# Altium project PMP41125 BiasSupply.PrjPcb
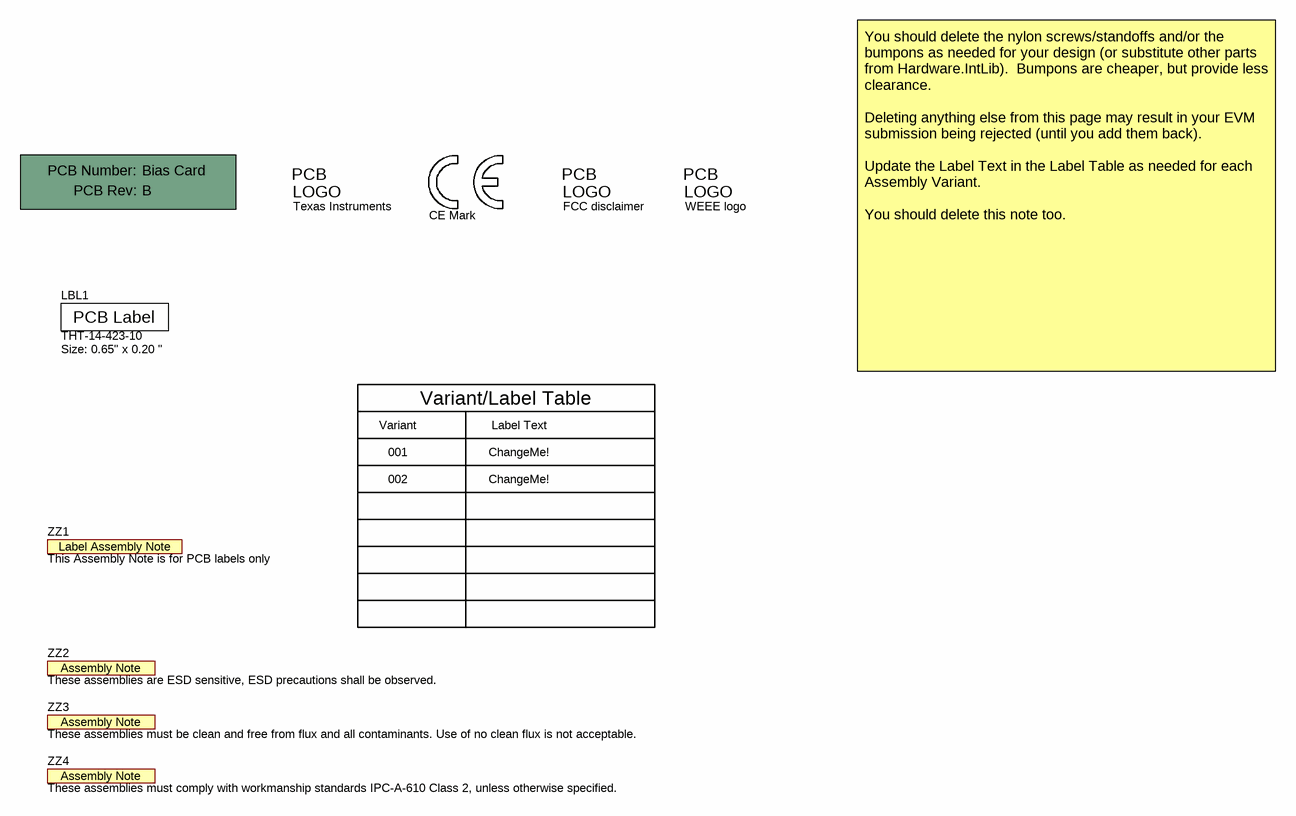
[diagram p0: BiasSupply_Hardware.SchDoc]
CopyrightYear: 2024; PCB_Layout: Daniel Gao; PCB_Rev: B; PRJ_Customer: Public Release; PRJ_Engineer: Forest Fu; PRJ_Number: Bias Card; PRJ_Title: HV-LV DCDC reference design; SCH_Rev: B; TechSupport: http://www.ti.com/support; TID: PMP41125
5 sheets, 169 parts. Net scope: flat (ports and power ports of the same name join across sheets).
Board file: BiasSupply.PcbDoc
Sheets:
  BiasSupply_Hardware.SchDoc
  BiasSupply-TPS552872-Q1.SchDoc
  BiasSupply-LM74202-Q1.SchDoc
  BiasSupply-SN6507-Q1.SchDoc
  BiasSupply-LM61440-Q1.SchDoc

## Sheet BiasSupply_Hardware.SchDoc
size 431 x 279 mm; Date: Not shown in title block; ApprovedBy: Not shown in title block; CheckedBy: Not shown in title block; Author: Not shown in title block; CompanyName: Not shown in title block; Engineer: Not shown in title block; Organization: Not shown in title block; Address1: Not shown in title block; Address2: Not shown in title block; Address3: Not shown in title block; Address4: Not shown in title block; DocumentNumber: 3; Revision: Use project parameter SCH_Rev; SheetNumber: 3; SheetTotal: 3; PageSetup: Record=PageOptions¦CenterHorizontal=True¦CenterVertical=True¦PrintScale=1.00¦XCorrection=1.00¦YCorrection=1.00¦PrintKind=0¦BorderSize=5000000¦LeftOffset=0¦BottomOffset=0¦Orientation=2¦PaperLength=1000¦PaperWidth=1000¦Scale=100¦PaperSource=15¦PrintQuality=600¦MediaType=1¦DitherType=10¦PaperKind=Letter¦PrintScaleMode=1

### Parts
!PCB  Printed Circuit Board  (value not drawn)  (mechanical)
LBL1  THT-14-423-10  Note: Size: 0.65" x 0.20 "  [Label_650x200]
Logo1  Texas Instruments  [TI_Stacked_Overlay_Small]  (no BOM)
Logo2  CE Mark  [CE_Mark_5mm]  (no BOM)
Logo3  FCC disclaimer  [FCC_disclaimer]  (no BOM)
Logo4  WEEE logo  [WEEE_Minimum]  (no BOM)
ZZ1  This Assembly Note is for PCB labels only  [AssemblyNoteLabel]  (no BOM)
ZZ2  These assemblies are ESD sensitive, ESD precautions shall be observed.  [AssemblyNote]  (no BOM)
ZZ3  These assemblies must be clean and free from flux and all contaminants. Use of no clean flux is not acceptable.  [AssemblyNote]  (no BOM)
ZZ4  These assemblies must comply with workmanship standards IPC-A-610 Class 2, unless otherwise specified.  [AssemblyNote]  (no BOM)

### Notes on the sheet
- Variant
- Variant/Label Table
- Label Text
- You should delete the nylon screws/standoffs and/or the bumpons as needed for your design (or substitute other parts from Hardware.IntLib).  Bumpons are cheaper, but provide less clearance.
  Deleting anything else from this page may result in your EVM submission being rejected (until you add them back).
  Update the Label Text in the Label Table as needed for each Assembly Variant.
  You should delete this note too.
- 001
- 002
- ChangeMe!

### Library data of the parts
!PCB = CMP-0003618-2: Manufacturer: Any; PartNumber: Bias Card
LBL1 = CMP-0003625-1: Thermal Transfer Printable Labels, 0.650" W x 0.200" H - 10,000 per roll; Manufacturer: Brady; CompType: Label
Logo1 = CMP-0074838-1: Texas Instrument Corporate Signature; SymbolCreator: a0412235; Lib Reference: TI_Logo; Library Reference: Logo
Logo2 = CMP-0074844-1: SymbolCreator: a0412235
Logo3 = CMP-0074847-1: FCC_disclaimer; Library Reference: Logo
Logo4 = CMP-0074769-1
ZZ1 = CMP-0003616-3
ZZ2 = CMP-0077236-1
ZZ3 = CMP-0077237-1
ZZ4 = CMP-0077238-1

## Sheet BiasSupply-TPS552872-Q1.SchDoc
size 431 x 279 mm; Date: Not shown in title block; ApprovedBy: Not shown in title block; CheckedBy: Not shown in title block; Author: Not shown in title block; CompanyName: Not shown in title block; DrawnBy: Daniel Gao; Engineer: Not shown in title block; Organization: Not shown in title block; Address1: Not shown in title block; Address2: Not shown in title block; Address3: Not shown in title block; Address4: Not shown in title block; DocumentNumber: 2; Revision: Use project parameter SCH_Rev; SheetNumber: 2; SheetTotal: 3; PageSetup: Record=PageOptions¦CenterHorizontal=True¦CenterVertical=True¦PrintScale=1.00¦XCorrection=1.00¦YCorrection=1.00¦PrintKind=0¦BorderSize=5000000¦LeftOffset=0¦BottomOffset=0¦Orientation=2¦PaperLength=1000¦PaperWidth=1000¦Scale=100¦PaperSource=15¦PrintQuality=600¦MediaType=1¦DitherType=10¦PaperKind=Letter¦PrintScaleMode=1
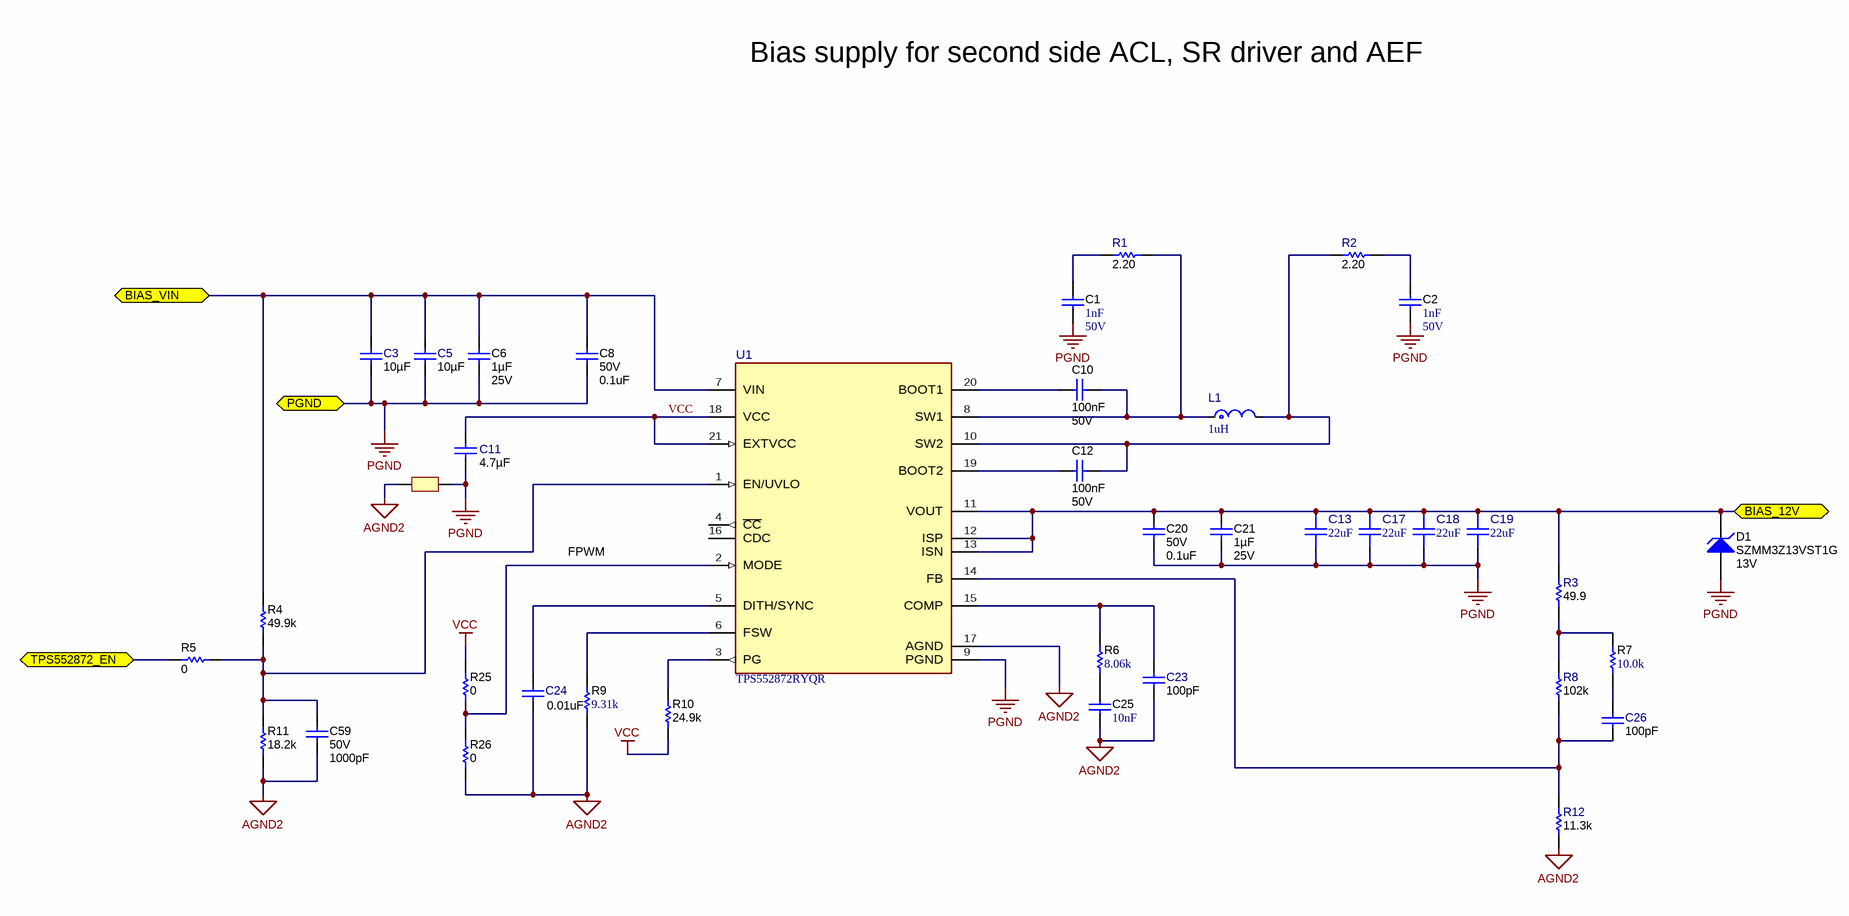
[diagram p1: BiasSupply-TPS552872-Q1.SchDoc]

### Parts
C1  Cap_F: 1nF  VDC_V: 50V  [0603]  (hidden comment: C0603C102J5RACAUTO)
C2  Cap_F: 1nF  VDC_V: 50V  [0603]  (hidden comment: C0603C102J5RACAUTO)
C3  ValueDisplayed: 10µF  [1206_190]  (hidden comment: CGA5L1X7R1H106K160AC)
C5  ValueDisplayed: 10µF  [1206_190]  (hidden comment: CGA5L1X7R1H106K160AC)
C6  Cap_F: 1µF  VDC_V: 25V  [0603L]  (hidden comment: CGA3E1X7R1E105K080AC)
C8  VDC_V: 50V  ValueDisplayed: 0.1uF  [0402]  (hidden comment: GCM155R71H104KE02D)
C10  Cap_F: 100nF  VDC_V: 50V  [0603L]  (hidden comment: CGA3E2X7R1H104K080AA)
C11  ValueDisplayed: 4.7µF  [0603]  (hidden comment: GRT188R61C475KE13D)
C12  Cap_F: 100nF  VDC_V: 50V  [0603L]  (hidden comment: CGA3E2X7R1H104K080AA)
C13  ValueDisplayed: 22uF  [FP-CGA6P3X7R1E226M250AB_1210-MFG]  (hidden comment: CGA6P3X7R1E226M250AB)
C17  ValueDisplayed: 22uF  [FP-CGA6P3X7R1E226M250AB_1210-MFG]  (hidden comment: CGA6P3X7R1E226M250AB)
C18  ValueDisplayed: 22uF  [FP-CGA6P3X7R1E226M250AB_1210-MFG]  (hidden comment: CGA6P3X7R1E226M250AB)
C19  ValueDisplayed: 22uF  [FP-CGA6P3X7R1E226M250AB_1210-MFG]  (hidden comment: CGA6P3X7R1E226M250AB)
C20  VDC_V: 50V  ValueDisplayed: 0.1uF  [0402]  (hidden comment: GCM155R71H104KE02D)
C21  Cap_F: 1µF  VDC_V: 25V  [0603L]  (hidden comment: CGA3E1X7R1E105K080AC)
C23  ValueDisplayed: 100pF  [0402]  (hidden comment: Capacitor)
C24  ValueDisplayed: 0.01uF  [0402]  (hidden comment: CGA2B3X7R1H103K050BB)
C25  ValueDisplayed: 10nF  [0402]  (hidden comment: CGA2B3X7R1H103K050BB)
C26  ValueDisplayed: 100pF  [0402]  (hidden comment: Capacitor)
C59  VDC_V: 50V  ValueDisplayed: 1000pF  [0402]  (hidden comment: GCM155R71H102KA37D)
D1  SZMM3Z13VST1G  value 13V  [SOD-323]
L1  value 1uH  [FP-XGL5030-102MEC_SMT_IND_5MM28_5MM48-MFG]  (hidden comment: XGL5030-102MEC)
NT1  Net-Tie  [Net-Tie_50milWide_30milLong]  (value not drawn)  (net tie, no BOM)
R1  ValueDisplayed: 2.20  [1206]  (hidden comment: Resistor)
R2  ValueDisplayed: 2.20  [1206]  (hidden comment: Resistor)
R3  ValueDisplayed: 49.9  [0402]  (hidden comment: Resistor)
R4  ValueDisplayed: 49.9k  [0402]  (hidden comment: CRCW040249K9FKED)
R5  ValueDisplayed: 0  [0402]  (hidden comment: CRCW04020000Z0ED)
R6  ValueDisplayed: 8.06k  [0402]  (hidden comment: CRCW04028K06FKED)
R7  ValueDisplayed: 10.0k  [0402]  (hidden comment: CRCW040210K0FKED)
R8  ValueDisplayed: 102k  [0402]  (hidden comment: Resistor)
R9  ValueDisplayed: 9.31k  [0402]  (hidden comment: CRCW04029K31FKED)
R10  ValueDisplayed: 24.9k  [0402]  (hidden comment: CRCW040224K9FKED)
R11  ValueDisplayed: 18.2k  [0402]  (hidden comment: CRCW040218K2FKED)
R12  ValueDisplayed: 11.3k  [0402]  (hidden comment: Resistor)
R25  ValueDisplayed: 0  [0402]  (hidden comment: CRCW04020000Z0ED)
R26  ValueDisplayed: 0  [0402]  (hidden comment: CRCW04020000Z0ED)
U1  TPS552872RYQR  [RYQ0021A-MFG]

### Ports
BIAS_12V (bidir), BIAS_VIN (bidir), PGND (bidir), TPS552872_EN (bidir)

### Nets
AGND2: C23.2 C24.2 C25.2 C59.2 NT1.1 R9.1 R11.1 R12.1 R26.1 U1.17(AGND)
PGND: C1.2 C2.2 C3.2 C5.2 C6.1 C8.2 C11.2 C13.2 C17.2 C18.2 C19.2 C20.2 C21.1 D1.2(A) NT1.2 U1.9(PGND) ; port PGND
VCC: C11.1 R10.1 R25.2 U1.18(VCC) U1.21(EXTVCC)
BIAS_12V: C13.1 C17.1 C18.1 C19.1 C20.1 C21.2 D1.1(K) R3.2 U1.11(VOUT) U1.12(ISP) U1.13(ISN) ; port BIAS_12V
BIAS_VIN: C3.1 C5.1 C6.2 C8.1 R4.2 U1.7(VIN) ; port BIAS_VIN
TPS552872_EN: R5.1 ; port TPS552872_EN
NetC1_1: C1.1 R1.2
NetC2_1: C2.1 R2.1
NetC10_1: C10.1 L1.1 R1.1 U1.8(SW1)
NetC10_2: C10.2 U1.20(BOOT1)
NetC12_1: C12.1 L1.2 R2.2 U1.10(SW2)
NetC12_2: C12.2 U1.19(BOOT2)
NetC23_1: C23.1 R6.2 U1.15(COMP)
NetC24_1: C24.1 U1.5(DITH/SYNC)
NetC25_1: C25.1 R6.1
NetC26_1: C26.1 R7.1
NetC26_2: C26.2 R8.1 R12.2 U1.14(FB)
NetC59_1: C59.1 R4.1 R5.2 R11.2 U1.1(EN/UVLO)
NetR3_1: R3.1 R7.2 R8.2
NetR9_2: R9.2 U1.6(FSW)
NetR10_2: R10.2 U1.3(PG)
NetR25_1: R25.1 R26.2 U1.2(MODE)

Not connected (* = marked no-connect by the designer): U1 4(~{CC}) 16(CDC)

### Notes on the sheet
- Bias supply for second side ACL, SR driver and AEF
- FPWM

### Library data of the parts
C1 C2 = CMP-0006844-4: CAP, CERM, 1000 pF, 50 V, +/- 5%, X7R, AEC-Q200 Grade 1, 0603; Manufacturer: Kemet; TaMin_C: -55°C; Polarized: N; SizeAreaWB_mm2: 4.68; Value1: Unknown; U/M: EA; Value: 1000pF; TaMax_C: 125°C; SizeZ_mm: 1; SizeX_mm: 1.6; SizeY_mm: 0.8; SizeArea_mm2: 1.28; AEC Qualified: Y; AEC Category: Q200
C3 C5 = CMP-0085950-1: CAP, CERM, 10 µF, 50 V,+/- 10%, X7R, AEC-Q200 Grade 1, 1206; Manufacturer: TDK; SizeZ_mm: 1.9; Value: 10uF; Value2: 50V; Cap_Case: 1206; AEC Grade: 1; TaMin_C: -55°C; U/M: EA; CompType: Capacitor; SizeArea_mm2: 5.12; TaMax_C: 125°C; AEC Qualified: Y; AEC Category: Q200; SizeX_mm: 3.2; SizeY_mm: 1.6; Polarized: N; SizeAreaWB_mm2: 10.92
C6 C21 = CMP-0076705-2: CAP, CERM, 1 µF, 25 V,+/- 10%, X7R, AEC-Q200 Grade 1, 0603; Manufacturer: TDK; SizeAreaWB_mm2: 4.68; SizeArea_mm2: 1.28; AEC Qualified: Y; AEC Category: Q200; Value: 1uF; TaMax_C: 125°C; SizeZ_mm: 1.0; AEC Grade: 1; Polarized: N; TaMin_C: -55°C; SizeY_mm: 0.8; U/M: EA; SizeX_mm: 1.6; Cap_Case: 1.6x0.8x0.8mm
C8 C20 = CMP-0006356-2: CAP, CERM, 0.1 uF, 50 V, +/- 10%, X7R, AEC-Q200 Grade 1, 0402; Manufacturer: MuRata; TaMin_C: -55°C; Polarized: N; SizeAreaWB_mm2: 3; Value1: Unknown; U/M: EA; Value: 0.1uF; TaMax_C: 125°C; SizeZ_mm: 0.6; SizeX_mm: 1; SizeY_mm: 0.5; AEC Qualified: Y; Cap_F: 100nF; AEC Category: Q200
C10 C12 = CMP-0007078-1: CAP, CERM, 0.1 uF, 50 V, +/- 10%, X7R, AEC-Q200 Grade 1, 0603; Manufacturer: TDK; TaMin_C: -55°C; ESR_ohm: 29.6m; Polarized: N; SizeAreaWB_mm2: 4.68; Value1: 0.0296 ohm; U/M: EA; Value: 0.1uF; TaMax_C: 125°C; SizeZ_mm: 1; SizeX_mm: 1.6; SizeY_mm: 0.8; Cap_Case: 0603; SizeArea_mm2: 1.28; AEC Qualified: Y; IRMS_A: 971.99mA; AEC Category: Q200
C11 = CMP-0081052-1: CAP, CERM, 4.7 µF, 16 V,+/- 10%, X5R, AEC-Q200 Grade 3, 0603; Manufacturer: MuRata; SizeAreaWB_mm2: 4.68; SizeArea_mm2: 1.28; AEC Qualified: Y; AEC Category: Q200; Value: 4.7uF; TaMax_C: 85°C; SizeZ_mm: 1; AEC Grade: 3; Polarized: N; TaMin_C: -55°C; VDC_V: 16V; SizeY_mm: 0.8; U/M: EA; CompType: Capacitor; SizeX_mm: 1.6
C13 C17-C19 = CMP-0036912-1: Cap Ceramic 22uF 25V X7R 20% Pad SMD 1210 +125°C Automotive T/R; Manufacturer: TDK; AEC Grade: Grade 1; AEC Qualified: Yes; Cap_F: 22µF; SizeZ_mm: 2.8mm; TempCo: 15%; Tolerance_%: 0.2%; Value: 22µF
C23 C26 = CMP-0006308-2: CAP, CERM, 100 pF, 50 V, +/- 5%, C0G/NP0, AEC-Q200 Grade 1, 0402; PartNumber: CGA2B2C0G1H101J050BA; Manufacturer: TDK; Polarized: N; Value: 100pF; U/M: EA; Value1: Unknown; VDC_V: 50V; TaMin_C: -55°C; TaMax_C: 125°C; SizeArea_mm2: 0.5; SizeAreaWB_mm2: 3; SizeX_mm: 1; SizeZ_mm: 0.6; AEC Category: Q200; AEC Qualified: Y
C24 = CMP-0006324-2: CAP, CERM, 0.01 uF, 50 V, +/- 10%, X7R, AEC-Q200 Grade 1, 0402; Manufacturer: TDK; TaMin_C: -55°C; ESR_ohm: 3.33065d; Polarized: N; SizeAreaWB_mm2: 3; Value1: 0.333065 ohm; U/M: EA; Value: 0.01uF; TaMax_C: 125°C; SizeZ_mm: 0.6; SizeX_mm: 1; SizeY_mm: 0.5; Value2: 50V; CompType: Capacitor; AEC Qualified: Y; Cap_F: 10nF; IRMS_A: 3.23373dA; AEC Category: Q200
C25 = CMP-0006324-2: CAP, CERM, 0.01 uF, 50 V, +/- 10%, X7R, AEC-Q200 Grade 1, 0402; Manufacturer: TDK; TaMin_C: -55°C; ESR_ohm: 0.3331; Polarized: N; SizeAreaWB_mm2: 3; Value1: 0.333065 ohm; U/M: EA; Value: 0.01uF; TaMax_C: 125°C; SizeZ_mm: 0.6; SizeX_mm: 1; SizeY_mm: 0.5; Value2: 50V; AEC Qualified: Y; IRMS_A: 323.373mA; AEC Category: Q200
C59 = CMP-0006354-2: CAP, CERM, 1000 pF, 50 V, +/- 10%, X7R, AEC-Q200 Grade 1, 0402; Manufacturer: MuRata; TaMin_C: -55°C; Polarized: N; SizeAreaWB_mm2: 3; Value1: Unknown; U/M: EA; Value: 1000pF; TaMax_C: 125°C; SizeZ_mm: 0.6; SizeX_mm: 1; SizeY_mm: 0.5; AEC Qualified: Y; Cap_F: 1nF; AEC Category: Q200
D1 = CMP-0085759-1: Diode, Zener, 13 V, 300 mW, AEC-Q101, SOD-323; Manufacturer: ON Semiconductor; AEC Category: Q101; RJA_CperW: 416; SizeX_mm: 2.7; SizeAreaWB_mm2: 8.695; SizeZ_mm: 1; SizeArea_mm2: 3.645; AEC Qualified: Y; SizeY_mm: 1.35; Value1: 0.3W; Power_W: 300mW
L1 = CMP-0091978-1: Shielded Power Inductor, 1uH, 20%, 17.8A IRMS, 5.8mOhm DCR max, AECQ200 Grade1, 5.28x5.48x3.1mm; Manufacturer: Coilcraft; Test Frequency: 1MHz; Shrouded: true; DCR_ohm: 5.8m; Ind_H: 1µH; Material: Composite; TaMin_C: -40°C; TaMax_C: +125°C; Self Resonant Frequency: 52MHz; AEC Qualified: Yes; Isat: 5.9A; SizeZ_mm: 3.1mm
NT1 = CMP-0078142-6: Single point connection between nets.
R1 R2 = CMP-0017777-3: RES, 2.20, 1%, 0.25 W, AEC-Q200 Grade 0, 1206; PartNumber: ERJ-8RQF2R2V; Manufacturer: Panasonic; Value: 2.20; Res_ohm: 2.2; Value_Code: 2R20; Power_W: 250mW; Value2: 0.25W; TempCo: 200 ppm/C; SizeArea_mm2: 5.12; SizeX_mm: 3.2; SizeY_mm: 1.6; SizeZ_mm: 1.35; AEC Category: Q200; AEC Qualified: Y; AEC Grade: 0; SizeAreaWB_mm2: 10.92
R3 = CMP-0026404-2: RES, 49.9, 1%, 0.063 W, AEC-Q200 Grade 0, 0402; PartNumber: CRCW040249R9FKED; Manufacturer: Vishay-Dale; Value: 49.9; Value_Code: 49R9; Power_W: 63mW; Value2: 0.063W; VDC_V: 50V; TempCo: 100 ppm/C; EIA_Code: E96; AEC Category: Q200; AEC Grade: 0; AEC Qualified: Y; SizeArea_mm2: 0.5; SizeX_mm: 1; SizeZ_mm: 0.6
R4 = CMP-0026403-2: RES, 49.9 k, 1%, 0.063 W, AEC-Q200 Grade 0, 0402; Manufacturer: Vishay-Dale; Power_W: 63mW; TempCo: 100 ppm/C; Value_Code: 49k9; Value: 49.9k; EIA_Code: E96; SizeX_mm: 1; SizeY_mm: 0.5; SizeZ_mm: 0.6; Value2: 0.063W; AEC Qualified: Y; VDC_V: 50V; AEC Category: Q200; AEC Grade: 0
R5 R25 R26 = CMP-0026822-3: RES, 0, 5%, 0.063 W, AEC-Q200 Grade 0, 0402; Manufacturer: Vishay-Dale; Power_W: 63mW; TempCo: 200 ppm/C; Value_Code: 0000; Value: 0; EIA_Code: E24; SizeX_mm: 1; SizeY_mm: 0.5; SizeZ_mm: 0.6; Value2: 0.063W; AEC Qualified: Y; VDC_V: 50V; AEC Category: Q200
R6 = CMP-0026588-2: RES, 8.06 k, 1%, 0.063 W, AEC-Q200 Grade 0, 0402; Manufacturer: Vishay-Dale; Power_W: 63mW; TempCo: 100 ppm/C; Value_Code: 8k06; Value: 8.06k; EIA_Code: E96; SizeX_mm: 1; SizeY_mm: 0.5; SizeZ_mm: 0.6; Value2: 0.063W; AEC Qualified: Y; VDC_V: 50V; AEC Category: Q200; AEC Grade: 0
R7 = CMP-0025958-3: RES, 10.0 k, 1%, 0.063 W, AEC-Q200 Grade 0, 0402; Manufacturer: Vishay-Dale; Power_W: 63mW; TempCo: 100 ppm/C; Value_Code: 10k0; Value: 10.0k; EIA_Code: E96; Res_ohm: 10k; SizeX_mm: 1; SizeY_mm: 0.5; SizeZ_mm: 0.6; Value2: 0.063W; AEC Qualified: Y; VDC_V: 50V; AEC Category: Q200; AEC Grade: 0
R8 = CMP-0025952-3: RES, 102 k, 1%, 0.063 W, AEC-Q200 Grade 0, 0402; PartNumber: CRCW0402102KFKED; Manufacturer: Vishay-Dale; Value: 102k; Power_W: 63mW; Value2: 0.063W; VDC_V: 50V; TempCo: 100 ppm/C; SizeArea_mm2: 0.5; SizeX_mm: 1; SizeZ_mm: 0.6; EIA_Code: E96; AEC Category: Q200; AEC Qualified: Y; AEC Grade: 0
R9 = CMP-0026620-3: RES, 9.31 k, 1%, 0.063 W, AEC-Q200 Grade 0, 0402; Manufacturer: Vishay-Dale; Power_W: 63mW; TempCo: 100 ppm/C; Value_Code: 9k31; Value: 9.31k; EIA_Code: E96; SizeX_mm: 1; SizeY_mm: 0.5; SizeZ_mm: 0.6; Value2: 0.063W; AEC Qualified: Y; VDC_V: 50V; AEC Category: Q200; AEC Grade: 0
R10 = CMP-0026196-2: RES, 24.9 k, 1%, 0.063 W, AEC-Q200 Grade 0, 0402; Manufacturer: Vishay-Dale; Power_W: 63mW; TempCo: 100 ppm/C; Value_Code: 24k9; Value: 24.9k; EIA_Code: E96; SizeX_mm: 1; SizeY_mm: 0.5; SizeZ_mm: 0.6; Value2: 0.063W; AEC Qualified: Y; VDC_V: 50V; AEC Category: Q200; AEC Grade: 0
R11 = CMP-0026059-3: RES, 18.2 k, 1%, 0.063 W, AEC-Q200 Grade 0, 0402; Manufacturer: Vishay-Dale; Power_W: 63mW; TempCo: 100 ppm/C; Value_Code: 18k2; Value: 18.2k; EIA_Code: E96; SizeX_mm: 1; SizeY_mm: 0.5; SizeZ_mm: 0.6; Value2: 0.063W; AEC Qualified: Y; VDC_V: 50V; AEC Category: Q200; AEC Grade: 0
R12 = CMP-0025976-3: RES, 11.3 k, 1%, 0.063 W, AEC-Q200 Grade 0, 0402; PartNumber: CRCW040211K3FKED; Manufacturer: Vishay-Dale; Value: 11.3k; Value_Code: 11k3; Power_W: 63mW; Value2: 0.063W; VDC_V: 50V; TempCo: 100 ppm/C; SizeArea_mm2: 0.5; SizeX_mm: 1; SizeZ_mm: 0.6; EIA_Code: E96; AEC Category: Q200; AEC Qualified: Y; AEC Grade: 0
U1 = CMP-0032941-1: Automotive, 36-V, 4-Switch, Integrated Buck-boost Converter; Manufacturer: Texas Instruments; SizeZ_mm: 1mm; AEC Qualified: Yes; AEC Grade: Grade 1; Max Supply Voltage: 36V; Min Supply Voltage: 3V; Nominal Supply Current: 760uA; Number Of Outputs: 1; Output Type: AdjustableProgrammable; Output Voltage: 0.8-22V; Standoff Height: 0mm; Switching Frequency: 200-2200kHz; TaMax_C: +125°C; TaMin_C: -40°C

## Sheet BiasSupply-LM74202-Q1.SchDoc
size 431 x 279 mm; Date: Not shown in title block; ApprovedBy: Not shown in title block; CheckedBy: Not shown in title block; Author: Not shown in title block; CompanyName: Not shown in title block; Engineer: Not shown in title block; Organization: Not shown in title block; Address1: Not shown in title block; Address2: Not shown in title block; Address3: Not shown in title block; Address4: Not shown in title block; DocumentNumber: 1; Revision: Use project parameter SCH_Rev; SheetNumber: 1; SheetTotal: 3; PageSetup: Record=PageOptions¦CenterHorizontal=True¦CenterVertical=True¦PrintScale=1.00¦XCorrection=1.00¦YCorrection=1.00¦PrintKind=0¦BorderSize=5000000¦LeftOffset=0¦BottomOffset=0¦Orientation=2¦PaperLength=1000¦PaperWidth=1000¦Scale=100¦PaperSource=15¦PrintQuality=600¦MediaType=1¦DitherType=10¦PaperKind=Letter¦PrintScaleMode=1
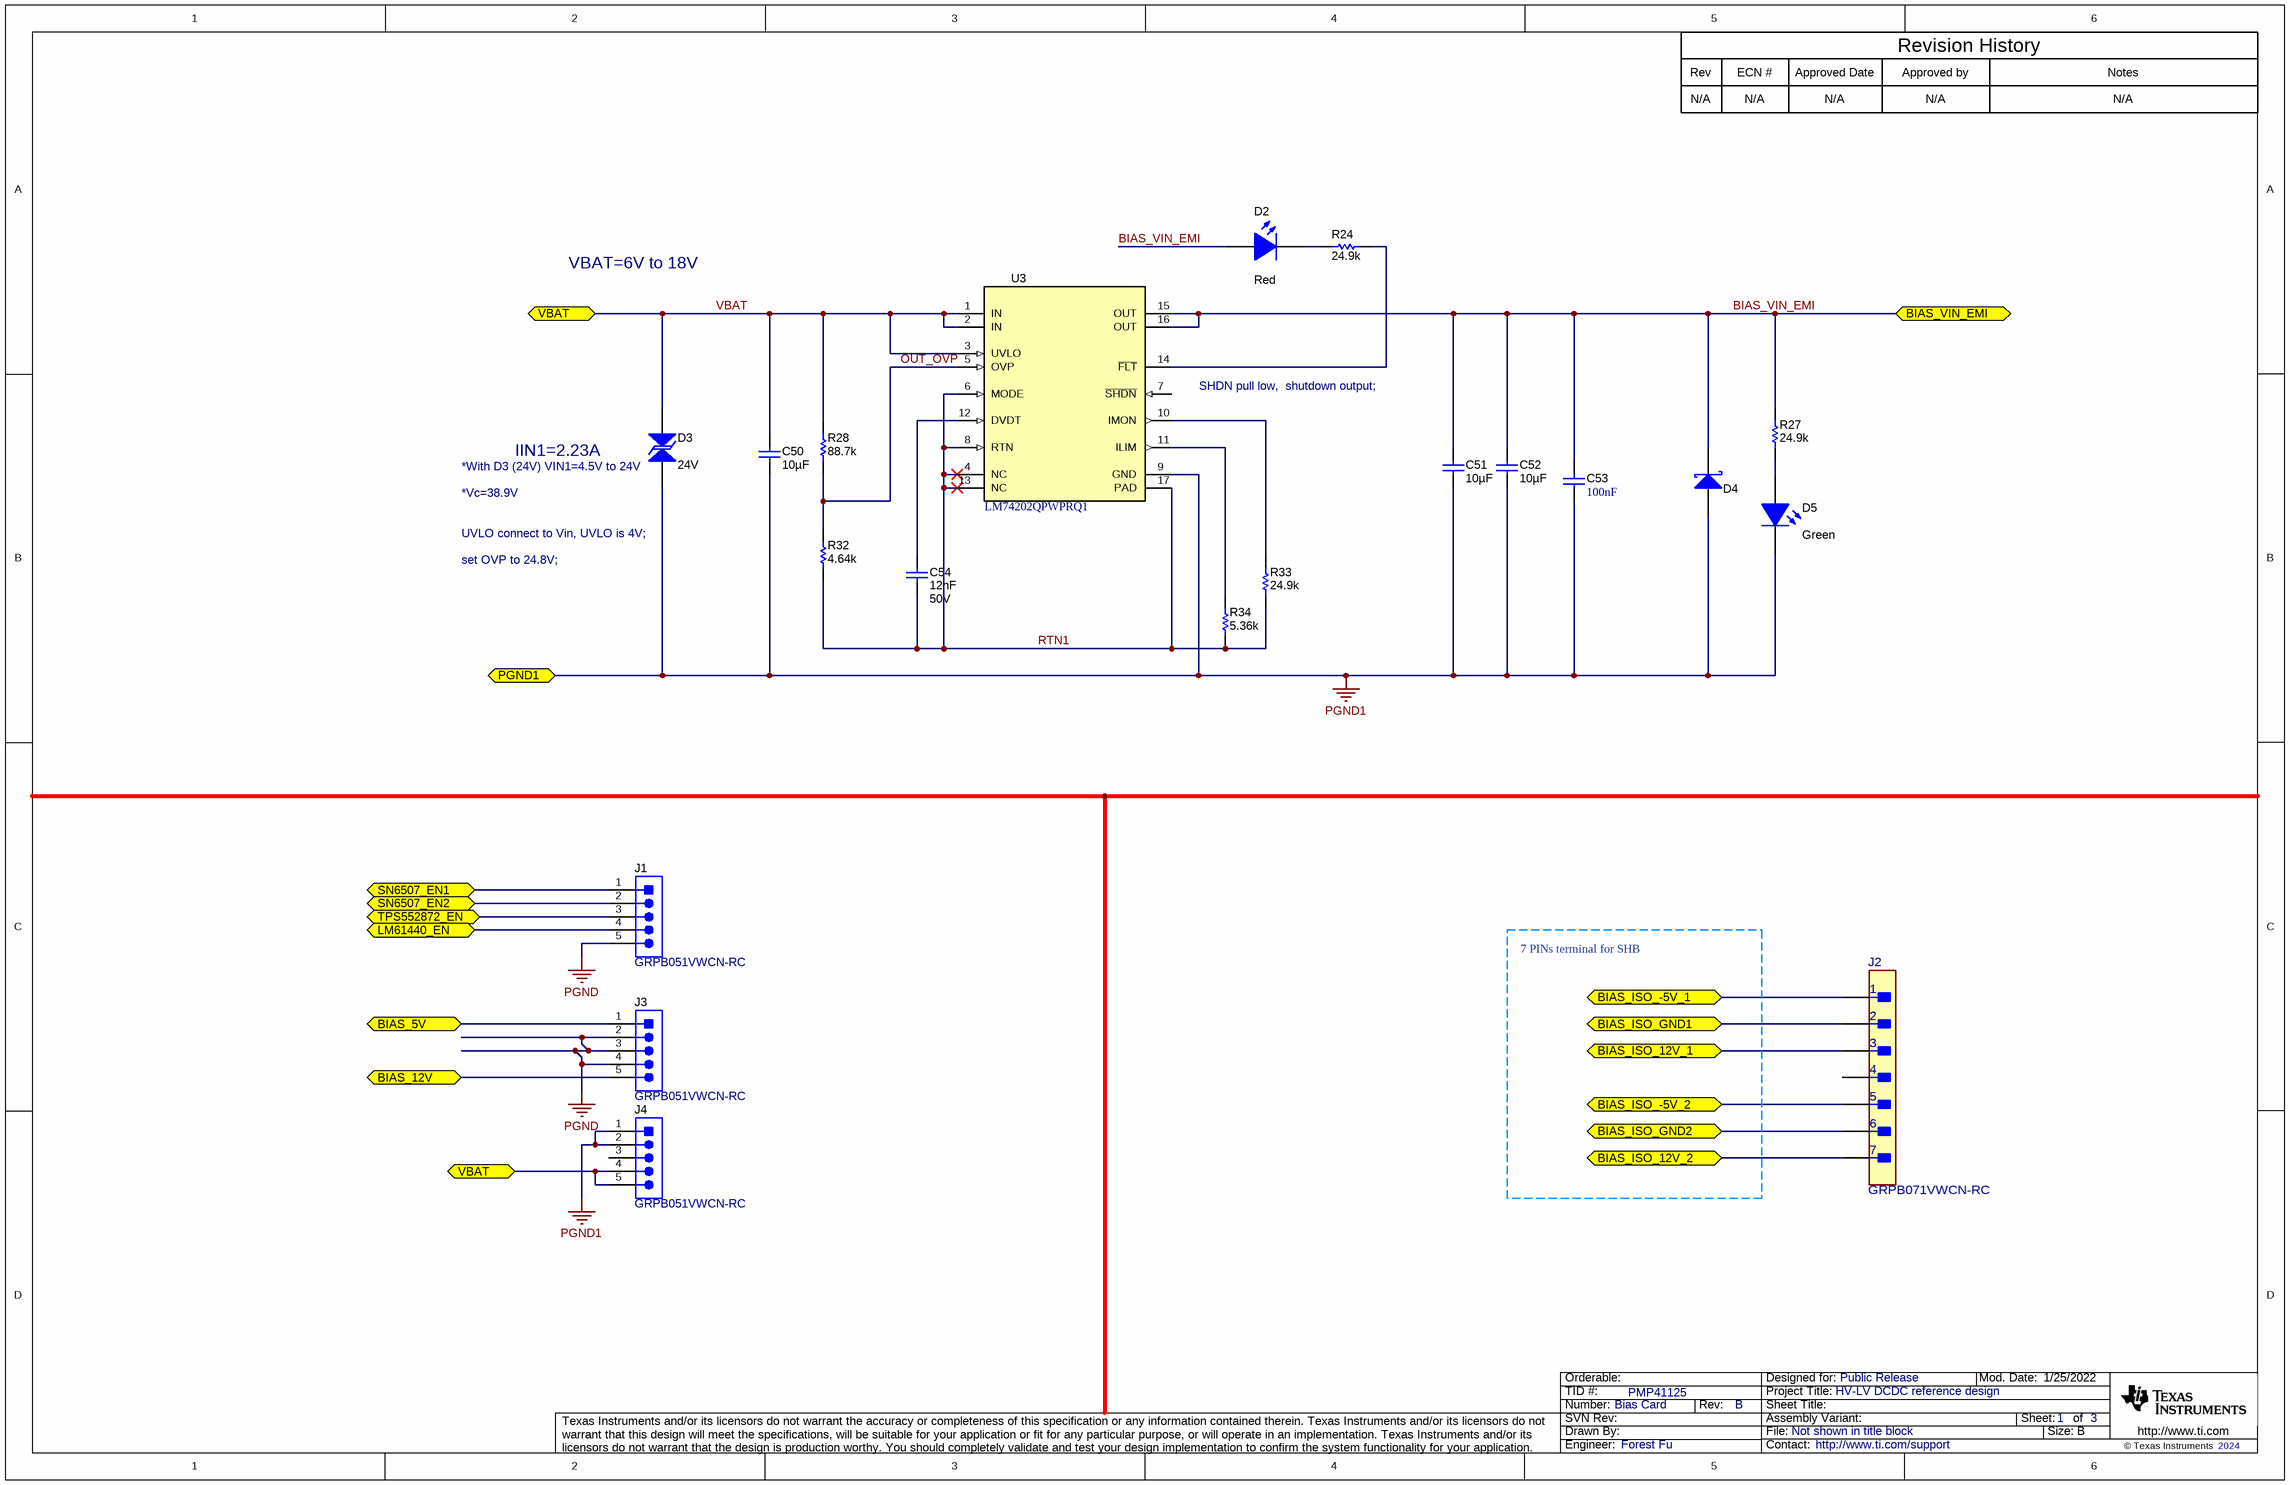
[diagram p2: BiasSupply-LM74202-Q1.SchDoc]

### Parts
C50  ValueDisplayed: 10µF  [1206_190]  (hidden comment: CGA5L1X7R1H106K160AC)
C51  ValueDisplayed: 10µF  [1206_190]  (hidden comment: CGA5L1X7R1H106K160AC)
C52  ValueDisplayed: 10µF  [1206_190]  (hidden comment: CGA5L1X7R1H106K160AC)
C53  Cap_F: 100nF  [0603]  (hidden comment: GCJ188R72A104KA01D)
C54  Cap_F: 12nF  VDC_V: 50V  [0603]  (hidden comment: C0603C123K5RACTU)
D2  value Red  [LED_LTST-C190_Red]  (hidden comment: CMP-0002842-2)
D3  value 24V  [SMA_Bi]  (hidden comment: SZ1SMA24CAT3G)
D4  PMEG6010CEGWJ  [SOD-123]  (value not drawn)
D5  value Green  [LED_LTST-C190]  (hidden comment: LTST-C190GKT)
J1  GRPB051VWCN-RC  [Sullins_xxxB051VWCN]
J2  GRPB071VWCN-RC  [FP-GRPB071VWCN-RC_HDR7-MFG]
J3  GRPB051VWCN-RC  [Sullins_xxxB051VWCN]
J4  GRPB051VWCN-RC  [Sullins_xxxB051VWCN]
R24  ValueDisplayed: 24.9k  [0402]  (hidden comment: CRCW040224K9FKED)
R27  ValueDisplayed: 24.9k  [0402]  (hidden comment: CRCW040224K9FKED)
R28  ValueDisplayed: 88.7k  [0402]  (hidden comment: CRCW040288K7FKED)
R32  ValueDisplayed: 4.64k  [0402]  (hidden comment: CRCW04024K64FKED)
R33  ValueDisplayed: 24.9k  [0402]  (hidden comment: CRCW040224K9FKED)
R34  ValueDisplayed: 5.36k  [0402]  (hidden comment: CRCW04025K36FKED)
U3  LM74202QPWPRQ1  [PWP0016H_L]

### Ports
BIAS_5V (bidir), BIAS_12V (bidir), BIAS_ISO_12V_1 (bidir), BIAS_ISO_12V_2 (bidir), BIAS_ISO_-5V_1 (bidir), BIAS_ISO_-5V_2 (bidir), BIAS_ISO_GND1 (bidir), BIAS_ISO_GND2 (bidir), BIAS_VIN_EMI (bidir), LM61440_EN (bidir), PGND1 (bidir), SN6507_EN1 (bidir), SN6507_EN2 (bidir), TPS552872_EN (bidir), VBAT (bidir)

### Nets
BIAS_ISO_GND1: J2.2 ; port BIAS_ISO_GND1
BIAS_ISO_GND2: J2.6 ; port BIAS_ISO_GND2
PGND: J1.5 J3.2 J3.3 J3.4
PGND1: C50.2 C51.2 C52.2 C53.2 D3.1 D4.2(A) D5.2(K) J4.1 J4.2 U3.9(GND) ; port PGND1
BIAS_5V: J3.1 ; port BIAS_5V
BIAS_12V: J3.5 ; port BIAS_12V
BIAS_ISO_12V_1: J2.3 ; port BIAS_ISO_12V_1
BIAS_ISO_12V_2: J2.7 ; port BIAS_ISO_12V_2
BIAS_ISO_-5V_1: J2.1 ; port BIAS_ISO_-5V_1
BIAS_ISO_-5V_2: J2.5 ; port BIAS_ISO_-5V_2
BIAS_VIN_EMI: C51.1 C52.1 C53.1 D2.1(A) D4.1(K) R27.2 U3.15(OUT) U3.16(OUT) ; port BIAS_VIN_EMI
LM61440_EN: J1.4 ; port LM61440_EN
OUT_OVP: R28.1 R32.2 U3.5(OVP)
RTN1: C54.2 R32.1 R33.1 R34.1 U3.4(NC) U3.6(MODE) U3.8(RTN) U3.13(NC) U3.17(PAD)
SN6507_EN1: J1.1 ; port SN6507_EN1
SN6507_EN2: J1.2 ; port SN6507_EN2
TPS552872_EN: J1.3 ; port TPS552872_EN
VBAT: C50.1 D3.2 J4.4 J4.5 R28.2 U3.1(IN) U3.2(IN) U3.3(UVLO) ; port VBAT
NetC54_1: C54.1 U3.12(DVDT)
NetD2_2: D2.2(K) R24.1
NetD5_1: D5.1(A) R27.1
NetR24_2: R24.2 U3.14(~{FLT})
NetR33_2: R33.2 U3.10(IMON)
NetR34_2: R34.2 U3.11(ILIM)

Not connected (* = marked no-connect by the designer): J2 4; J4 3; U3 7(~{SHDN})

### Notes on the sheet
- Rev
- N/A
- ECN #
- Approved Date
- Approved by
- Revision History
- Notes
- VBAT=6V to 18V
- SHDN pull low,  shutdown output;
- (near D3) *With D3 (24V) VIN1=4.5V to 24V
- *Vc=38.9V
- IIN1=2.23A
- UVLO connect to Vin, UVLO is 4V;
- set OVP to 24.8V;
- 7 PINs terminal for SHB

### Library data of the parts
C50-C52 = CMP-0085950-1: CAP, CERM, 10 µF, 50 V,+/- 10%, X7R, AEC-Q200 Grade 1, 1206; Manufacturer: TDK; SizeZ_mm: 1.9; Value: 10uF; Value2: 50V; Cap_Case: 1206; AEC Grade: 1; TaMin_C: -55°C; U/M: EA; SizeArea_mm2: 5.12; TaMax_C: 125°C; AEC Qualified: Y; AEC Category: Q200; SizeX_mm: 3.2; SizeY_mm: 1.6; Polarized: N; SizeAreaWB_mm2: 10.92
C53 = CMP-0064935-4: CAP, CERM, 0.1 uF, 100 V,+/- 10%, X7R, AEC-Q200 Grade 1, 0603; Manufacturer: MuRata; TaMin_C: -55°C; Polarized: N; SizeAreaWB_mm2: 4.68; Value1: Unknown; U/M: EA; Value: 0.1uF; TaMax_C: 125°C; SizeZ_mm: 1; SizeX_mm: 1.6; SizeY_mm: 0.8; Value2: 100V; SizeArea_mm2: 1.28; AEC Qualified: Y; AEC Category: Q200
C54 = CMP-0084236-1: CAP, CERM, 0.012 µF, 50 V,+/- 10%, X7R, AEC-Q200 Grade 1, 0603; Manufacturer: Kemet; TaMin_C: -55°C; Polarized: N; SizeAreaWB_mm2: 4.68; U/M: EA; Value: 0.012uF; TaMax_C: 125°C; SizeZ_mm: 1; SizeX_mm: 1.6; SizeY_mm: 0.8; SizeArea_mm2: 1.28; AEC Qualified: Y; AEC Category: Q200
D2 = CMP-0002842-2: LED, Red, SMD; Manufacturer: Lite-On; PartNumber: LTST-C190CKT; Vf_V: 2V; Io_A: 20mA; Tjmax_C: 85°C; Power_TotalModule: 62.5mW; Value1: 0.0625W
D3 = CMP-0085084-1: Diode, TVS, Bi, 24 V, 38.9 Vc, 400 W, 10.3 A, AEC-Q101, SMA (non-polarized); Manufacturer: Littelfuse; SizeZ_mm: 2.65; AEC Category: Q101; Vbr_Min: 26.7V; Value1: 38.9V; Ipp: 10.3A; AEC Qualified: Y; RJA_CperW: 250; SizeAreaWB_mm2: 32.368125; SizeArea_mm2: 13.068125; SizeX_mm: 5.075; SizeY_mm: 2.575; Ppk: 400W; Vbr_Max: 29.51V
D4 = CMP-0079239-2: Diode, Schottky, 60 V, 1 A, AEC-Q101, SOD-123; Manufacturer: Nexperia; SizeY_mm: 1.7; AEC Qualified: Y; SizeArea_mm2: 6.545; Vf_V: 660mV; Value: 60V; Value1: 1A; AEC Category: Q101; TJmax_C: 150°C; SizeX_mm: 3.85; SizeZ_mm: 1.35; SizeAreaWB_mm2: 13.095; Value2: 0.66V
D5 = CMP-0002827-3: LED, Green, SMD; Manufacturer: Lite-On; Vf_V: 2.1V; Io_A: 20mA; Power_TotalModule: 100mW; Value1: 0.1W
J1 J3 J4 = CMP-0054578-1: Header, 1.27 mm, 5x1, Gold, R/A, TH; Manufacturer: Sullins Connector Solutions; CNHeader: TRUE; Shrouded: N; Gender: Male; Row_Count: 1; Pitch_mm: 1.27; CT: FALSE
J2 = CMP-0121118-1: Manufacturer: Sullins; ContactFinish: Gold; Current_A: 1A; Row_Count: 1; AEC Qualified: No; Conn Gender: Male; Conn Orientation: Right Angle; DUT-Pitch_mm: 1.27mm; SizeZ_mm: 2.34mm
R24 R27 R33 = CMP-0026196-2: as R10 on sheet BiasSupply-TPS552872-Q1
R28 = CMP-0026586-2: RES, 88.7 k, 1%, 0.063 W, AEC-Q200 Grade 0, 0402; Manufacturer: Vishay-Dale; Power_W: 63mW; TempCo: 100 ppm/C; Value_Code: 88k7; Value: 88.7k; EIA_Code: E96; SizeX_mm: 1; SizeY_mm: 0.5; SizeZ_mm: 0.6; Value2: 0.063W; AEC Qualified: Y; VDC_V: 50V; AEC Category: Q200; AEC Grade: 0
R32 = CMP-0026411-2: RES, 4.64 k, 1%, 0.063 W, AEC-Q200 Grade 0, 0402; Manufacturer: Vishay-Dale; Power_W: 63mW; TempCo: 100 ppm/C; Value_Code: 4k64; Value: 4.64k; EIA_Code: E96; SizeX_mm: 1; SizeY_mm: 0.5; SizeZ_mm: 0.6; Value2: 0.063W; AEC Qualified: Y; VDC_V: 50V; AEC Category: Q200; AEC Grade: 0
R34 = CMP-0026465-2: RES, 5.36 k, 1%, 0.063 W, AEC-Q200 Grade 0, 0402; Manufacturer: Vishay-Dale; Power_W: 63mW; TempCo: 100 ppm/C; Value_Code: 5k36; Value: 5.36k; EIA_Code: E96; SizeX_mm: 1; SizeY_mm: 0.5; SizeZ_mm: 0.6; Value2: 0.063W; AEC Qualified: Y; VDC_V: 50V; AEC Category: Q200; AEC Grade: 0
U3 = CMP-0086101-2: 60V, 2A Integrated Ideal Diode with Over-Voltage & OverCurrent protection, PWP0016H (HTSSOP-16); Alternate Manufacturer: Texas Instruments; CompType: IC; SizeArea_mm2: 32; AEC Qualified: Y; AEC Category: Q200; SizeAreaWB_mm2: 58.8; SizeY_mm: 5; SizeZ_mm: 1.2; SizeX_mm: 6.4

## Sheet BiasSupply-SN6507-Q1.SchDoc
size 431 x 279 mm; Date: Not shown in title block; ApprovedBy: Not shown in title block; CheckedBy: Not shown in title block; Author: Not shown in title block; CompanyName: Not shown in title block; Engineer: Not shown in title block; Organization: Not shown in title block; Address1: Not shown in title block; Address2: Not shown in title block; Address3: Not shown in title block; Address4: Not shown in title block; DocumentNumber: 2; Revision: Use project parameter SCH_Rev; SheetNumber: 2; SheetTotal: 3; PageSetup: Record=PageOptions¦CenterHorizontal=True¦CenterVertical=True¦PrintScale=1.00¦XCorrection=1.00¦YCorrection=1.00¦PrintKind=0¦BorderSize=5000000¦LeftOffset=0¦BottomOffset=0¦Orientation=2¦PaperLength=1000¦PaperWidth=1000¦Scale=100¦PaperSource=15¦PrintQuality=600¦MediaType=1¦DitherType=10¦PaperKind=Letter¦PrintScaleMode=1
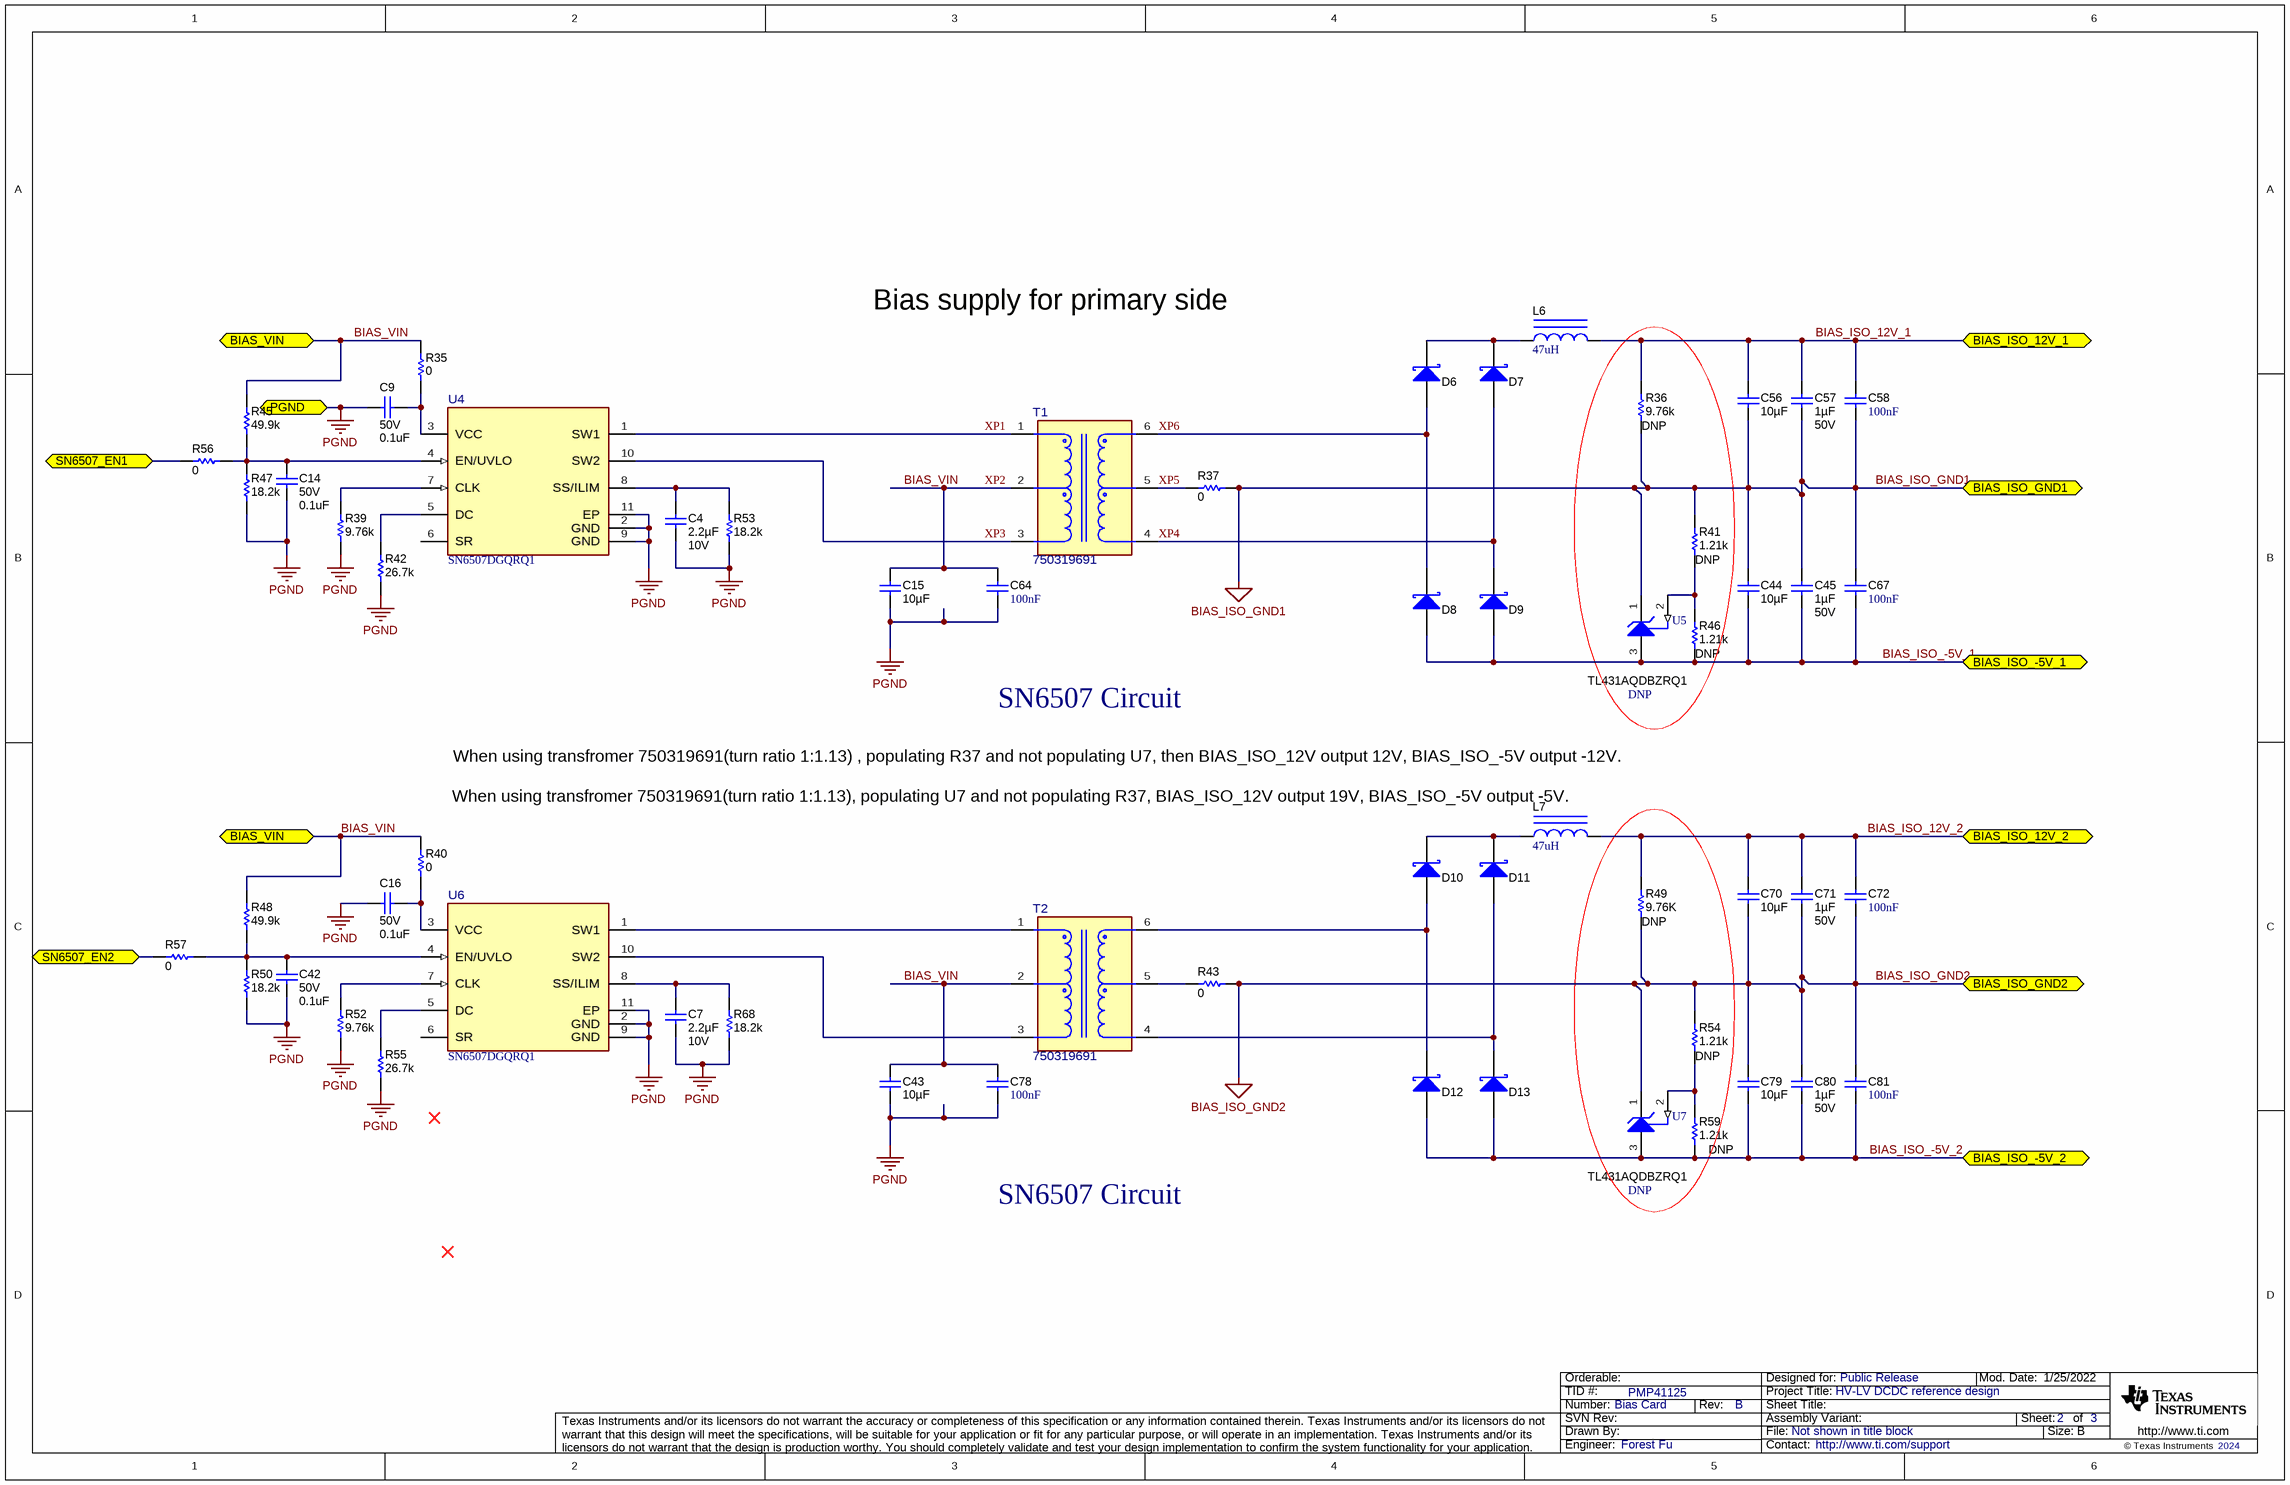
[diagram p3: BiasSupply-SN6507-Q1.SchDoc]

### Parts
C4  Cap_F: 2.2µF  VDC_V: 10V  [0603]  (hidden comment: GRM188R71A225KE15J)
C7  Cap_F: 2.2µF  VDC_V: 10V  [0603]  (hidden comment: GRM188R71A225KE15J)
C9  VDC_V: 50V  ValueDisplayed: 0.1uF  [0402]  (hidden comment: GCM155R71H104KE02D)
C14  VDC_V: 50V  ValueDisplayed: 0.1uF  [0402]  (hidden comment: GCM155R71H104KE02D)
C15  ValueDisplayed: 10µF  [1206_190]  (hidden comment: CGA5L1X7R1H106K160AC)
C16  VDC_V: 50V  ValueDisplayed: 0.1uF  [0402]  (hidden comment: GCM155R71H104KE02D)
C42  VDC_V: 50V  ValueDisplayed: 0.1uF  [0402]  (hidden comment: GCM155R71H104KE02D)
C43  ValueDisplayed: 10µF  [1206_190]  (hidden comment: CGA5L1X7R1H106K160AC)
C44  ValueDisplayed: 10µF  [1206_190]  (hidden comment: CGA5L1X7R1H106K160AC)
C45  Cap_F: 1µF  VDC_V: 50V  [0805_HV]  (hidden comment: GCM21BR71H105KA03K)
C56  ValueDisplayed: 10µF  [1206_190]  (hidden comment: CGA5L1X7R1H106K160AC)
C57  Cap_F: 1µF  VDC_V: 50V  [0805_HV]  (hidden comment: GCM21BR71H105KA03K)
C58  Cap_F: 100nF  [0603]  (hidden comment: GCJ188R72A104KA01D)
C64  Cap_F: 100nF  [0603]  (hidden comment: GCJ188R72A104KA01D)
C67  Cap_F: 100nF  [0603]  (hidden comment: GCJ188R72A104KA01D)
C70  ValueDisplayed: 10µF  [1206_190]  (hidden comment: CGA5L1X7R1H106K160AC)
C71  Cap_F: 1µF  VDC_V: 50V  [0805_HV]  (hidden comment: GCM21BR71H105KA03K)
C72  Cap_F: 100nF  [0603]  (hidden comment: GCJ188R72A104KA01D)
C78  Cap_F: 100nF  [0603]  (hidden comment: GCJ188R72A104KA01D)
C79  ValueDisplayed: 10µF  [1206_190]  (hidden comment: CGA5L1X7R1H106K160AC)
C80  Cap_F: 1µF  VDC_V: 50V  [0805_HV]  (hidden comment: GCM21BR71H105KA03K)
C81  Cap_F: 100nF  [0603]  (hidden comment: GCJ188R72A104KA01D)
D6  PMEG6010CEGWJ  [SOD-123]  (value not drawn)
D7  PMEG6010CEGWJ  [SOD-123]  (value not drawn)
D8  PMEG6010CEGWJ  [SOD-123]  (value not drawn)
D9  PMEG6010CEGWJ  [SOD-123]  (value not drawn)
D10  PMEG6010CEGWJ  [SOD-123]  (value not drawn)
D11  PMEG6010CEGWJ  [SOD-123]  (value not drawn)
D12  PMEG6010CEGWJ  [SOD-123]  (value not drawn)
D13  PMEG6010CEGWJ  [SOD-123]  (value not drawn)
L6  ValueDisplayed: 47uH  [SRN3015TA]  (hidden comment: SRN3015TA-470M)
L7  ValueDisplayed: 47uH  [SRN3015TA]  (hidden comment: SRN3015TA-470M)
R35  ValueDisplayed: 0  [0402]  (hidden comment: CRCW04020000Z0ED)
R36  DNP  ValueDisplayed: 9.76k  [0402]
R37  ValueDisplayed: 0  [0402]  (hidden comment: CRCW04020000Z0ED)
R39  ValueDisplayed: 9.76k  [0402]  (hidden comment: CRCW04029K76FKED)
R40  ValueDisplayed: 0  [0402]  (hidden comment: CRCW04020000Z0ED)
R41  DNP  ValueDisplayed: 1.21k  [0402]
R42  ValueDisplayed: 26.7k  [0402]  (hidden comment: CRCW040226K7FKED)
R43  ValueDisplayed: 0  [0402]  (hidden comment: CRCW04020000Z0ED)
R45  ValueDisplayed: 49.9k  [0402]  (hidden comment: CRCW040249K9FKED)
R46  DNP  ValueDisplayed: 1.21k  [0402]
R47  ValueDisplayed: 18.2k  [0402]  (hidden comment: CRCW040218K2FKED)
R48  ValueDisplayed: 49.9k  [0402]  (hidden comment: CRCW040249K9FKED)
R49  DNP  ValueDisplayed: 9.76K  [0402]
R50  ValueDisplayed: 18.2k  [0402]  (hidden comment: CRCW040218K2FKED)
R52  ValueDisplayed: 9.76k  [0402]  (hidden comment: CRCW04029K76FKED)
R53  ValueDisplayed: 18.2k  [0402]  (hidden comment: CRCW040218K2FKED)
R54  DNP  ValueDisplayed: 1.21k  [0402]
R55  ValueDisplayed: 26.7k  [0402]  (hidden comment: CRCW040226K7FKED)
R56  ValueDisplayed: 0  [0402]  (hidden comment: CRCW04020000Z0ED)
R57  ValueDisplayed: 0  [0402]  (hidden comment: CRCW04020000Z0ED)
R59  DNP  ValueDisplayed: 1.21k  [0402]
R68  ValueDisplayed: 18.2k  [0402]  (hidden comment: CRCW040218K2FKED)
T1  750319691  [FP-750319696_SMT_TRANSFORMER_9MM45_8MM50-MFG]
T2  750319691  [FP-750319696_SMT_TRANSFORMER_9MM45_8MM50-MFG]
U4  SN6507DGQRQ1  [DGQ0010D-MFG]
U5  DNP  PartNumber: TL431AQDBZRQ1  [DBZ0003A_N]
U6  SN6507DGQRQ1  [DGQ0010D-MFG]
U7  DNP  PartNumber: TL431AQDBZRQ1  [DBZ0003A_N]

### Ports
BIAS_ISO_12V_1 (bidir), BIAS_ISO_12V_2 (bidir), BIAS_ISO_-5V_1 (bidir), BIAS_ISO_-5V_2 (bidir), BIAS_ISO_GND1 (bidir), BIAS_ISO_GND2 (bidir), BIAS_VIN (bidir), PGND (bidir), SN6507_EN1 (bidir), SN6507_EN2 (bidir)

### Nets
BIAS_ISO_GND1: C44.1 C45.1 C56.2 C57.2 C58.2 C67.1 R36.1 R37.2 R41.2 U5.1(CATHODE) ; port BIAS_ISO_GND1
BIAS_ISO_GND2: C70.2 C71.2 C72.2 C79.1 C80.1 C81.1 R43.2 R49.1 R54.2 U7.1(CATHODE) ; port BIAS_ISO_GND2
PGND: C4.2 C7.2 C9.1 C14.2 C15.2 C16.1 C42.2 C43.2 C64.2 C78.2 R39.1 R42.1 R47.1 R50.1 R52.1 R53.1 R55.1 R68.1 U4.2(GND) U4.9(GND) U4.11(EP) U6.2(GND) U6.9(GND) U6.11(EP) ; port PGND
BIAS_ISO_12V_1: C56.1 C57.1 C58.1 L6.2 R36.2 ; port BIAS_ISO_12V_1
BIAS_ISO_12V_2: C70.1 C71.1 C72.1 L7.2 R49.2 ; port BIAS_ISO_12V_2
BIAS_ISO_-5V_1: C44.2 C45.2 C67.2 D8.2(A) D9.2(A) R46.1 U5.3(ANODE) ; port BIAS_ISO_-5V_1
BIAS_ISO_-5V_2: C79.2 C80.2 C81.2 D12.2(A) D13.2(A) R59.1 U7.3(ANODE) ; port BIAS_ISO_-5V_2
BIAS_VIN: C15.1 C43.1 C64.1 C78.1 R35.2 R40.2 R45.2 R48.2 T1.2 T2.2 ; port BIAS_VIN  [also labelled XP2]
SN6507_EN1: R56.1 ; port SN6507_EN1
SN6507_EN2: R57.1 ; port SN6507_EN2
XP1: T1.1 U4.1(SW1)
XP3: T1.3 U4.10(SW2)
XP4: D7.2(A) D9.1(K) T1.4
XP5: R37.1 T1.5
XP6: D6.2(A) D8.1(K) T1.6
NetC4_1: C4.1 R53.2 U4.8(SS/ILIM)
NetC7_1: C7.1 R68.2 U6.8(SS/ILIM)
NetC9_2: C9.2 R35.1 U4.3(VCC)
NetC14_1: C14.1 R45.1 R47.2 R56.2 U4.4(EN/UVLO)
NetC16_2: C16.2 R40.1 U6.3(VCC)
NetC42_1: C42.1 R48.1 R50.2 R57.2 U6.4(EN/UVLO)
NetD6_1: D6.1(K) D7.1(K) L6.1
NetD10_1: D10.1(K) D11.1(K) L7.1
NetD10_2: D10.2(A) D12.1(K) T2.6
NetD11_2: D11.2(A) D13.1(K) T2.4
NetR39_2: R39.2 U4.7(CLK)
NetR41_1: R41.1 R46.2 U5.2(REF)
NetR42_2: R42.2 U4.5(DC)
NetR43_1: R43.1 T2.5
NetR52_2: R52.2 U6.7(CLK)
NetR54_1: R54.1 R59.2 U7.2(REF)
NetR55_2: R55.2 U6.5(DC)
NetT2_1: T2.1 U6.1(SW1)
NetT2_3: T2.3 U6.10(SW2)

Not connected (* = marked no-connect by the designer): U4 6(SR); U6 6(SR)

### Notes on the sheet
- Bias supply for primary side
- SN6507 Circuit
- When using transfromer 750319691(turn ratio 1:1.13) , populating R37 and not populating U7, then BIAS_ISO_12V output 12V, BIAS_ISO_-5V output -12V.
- When using transfromer 750319691(turn ratio 1:1.13), populating U7 and not populating R37, BIAS_ISO_12V output 19V, BIAS_ISO_-5V output -5V.

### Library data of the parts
C4 C7 = CMP-0084284-1: CAP, CERM, 2.2 µF, 10 V,+/- 10%, X7R, AEC-Q200 Grade 1, 0603; Manufacturer: MuRata; SizeAreaWB_mm2: 4.68; Polarized: N; AEC Qualified: Y; SizeX_mm: 1.6; SizeZ_mm: 1; SizeY_mm: 0.8; U/M: EA; TaMin_C: -55°C; Value: 2.2uF; AEC Category: Q200; TaMax_C: 125°C; SizeArea_mm2: 1.28
C9 C14 C16 C42 = CMP-0006356-2: as C8 on sheet BiasSupply-TPS552872-Q1
C15 C43 C44 C56 C70 C79 = CMP-0085950-1: as C50 on sheet BiasSupply-LM74202-Q1
C45 C57 C71 C80 = CMP-0086249-1: CAP, CERM, 1 µF, 50 V,+/- 10%, X7R, AEC-Q200 Grade 1, 0805; Manufacturer: MuRata; Value: 1uF; AEC Qualified: Y; AEC Category: Q200; U/M: EA; AEC Grade: 1; SizeArea_mm2: 2.5; SizeAreaWB_mm2: 6.75; SizeZ_mm: 1.45; SizeX_mm: 2; Cap_Case: 0805; TaMax_C: 125°C; Polarized: N; SizeY_mm: 1.25; TaMin_C: -55°C
C58 C64 C67 C72 C78 C81 = CMP-0064935-4: as C53 on sheet BiasSupply-LM74202-Q1
D6-D13 = CMP-0079239-2: as D4 on sheet BiasSupply-LM74202-Q1
L6 L7 = CMP-0057653-2: Inductor, Shielded, Ferrite, 47 uH, 0.35 A, 1.44 ohm, AEC-Q200 Grade 1, SMD; Manufacturer: Bourns; Isat: 0.35A @ 30% inductance drop; Irms: 0.4A @ 40C rise; Green_Lifecycle: Active; SizeAreaWB_mm2: 16; DCR_ohm: 1.44; Green_REACh: Passed; Value: 47uH; Imax_A: 3.5dA; SizeZ_mm: 1.5; SizeX_mm: 3; Value2: 0.35A; SizeArea_mm2: 9; Ind_H: 47µH; AEC Qualified: Y; AEC Grade: 1; AEC Category: Q200
R35 R37 R40 R43 R56 R57 = CMP-0026822-3: as R5 on sheet BiasSupply-TPS552872-Q1
R36 R49 = CMP-0026622-3: RES, 9.76 k, 1%, 0.063 W, AEC-Q200 Grade 0, 0402; Manufacturer: Vishay-Dale; PartNumber: CRCW04029K76FKED; AEC Category: Q200; AEC Qualified: Y; AEC Grade: 0; Value2: 0.063W; Value_Code: 9k76; SizeY_mm: 0.5; SizeZ_mm: 0.6; VDC_V: 50V; SizeX_mm: 1; Value: 9.76k; Power_W: 63mW; EIA_Code: E96; TempCo: 100 ppm/C
R39 R52 = CMP-0026622-3: RES, 9.76 k, 1%, 0.063 W, AEC-Q200 Grade 0, 0402; Manufacturer: Vishay-Dale; AEC Category: Q200; AEC Qualified: Y; AEC Grade: 0; Value2: 0.063W; Value_Code: 9k76; SizeY_mm: 0.5; SizeZ_mm: 0.6; VDC_V: 50V; SizeX_mm: 1; Value: 9.76k; Power_W: 63mW; EIA_Code: E96; TempCo: 100 ppm/C
R41 R46 R54 R59 = CMP-0026079-3: RES, 1.21 k, 1%, 0.063 W, AEC-Q200 Grade 0, 0402; Manufacturer: Vishay-Dale; PartNumber: CRCW04021K21FKED; Power_W: 63mW; TempCo: 100 ppm/C; Value_Code: 1k21; Value: 1.21k; EIA_Code: E96; SizeX_mm: 1; SizeY_mm: 0.5; SizeZ_mm: 0.6; Value2: 0.063W; AEC Qualified: Y; VDC_V: 50V; AEC Category: Q200; AEC Grade: 0
R42 R55 = CMP-0026208-2: RES, 26.7 k, 1%, 0.063 W, AEC-Q200 Grade 0, 0402; Manufacturer: Vishay-Dale; Power_W: 63mW; TempCo: 100 ppm/C; Value_Code: 26k7; Value: 26.7k; EIA_Code: E96; SizeX_mm: 1; SizeY_mm: 0.5; SizeZ_mm: 0.6; Value2: 0.063W; AEC Qualified: Y; VDC_V: 50V; AEC Category: Q200; AEC Grade: 0
R45 R48 = CMP-0026403-2: as R4 on sheet BiasSupply-TPS552872-Q1
R47 R50 R53 R68 = CMP-0026059-3: as R11 on sheet BiasSupply-TPS552872-Q1
T1 T2 = CMP-0092994-1: TRANSFORMER; Manufacturer: Wurth; Frequency_Fixed: 1MHz; Ns1toNp: 1.38:1; AEC Qualified: No; SizeZ_mm: 5mm
U4 U6 = CMP-0092987-2: Low-Noise 36V Push-Pull Transformer Driver with Duty Cycle Control for Isolated Power Supplies; Manufacturer: Texas Instruments; TaMin_C: -55°C; TaMax_C: +125°C; Standoff Height: 0.05mm; TJmax_C: +150°C; SizeZ_mm: 1.1mm; AEC Qualified: No; CompType: IC; AEC Category: Q200
U5 U7 = CMP-0033164-1: Automotive Catalog Adjustable Precision Shunt Regulator, 34 ppm / degC, 100 mA, -40 to 125 degC, 3-pin SOT-23 (DBZ), Green (RoHS & no Sb/Br); Manufacturer: Texas Instruments; SubFamily: Shunt Voltage Reference; Initial Accuracy @ 25/deg C(%): 1; Min Iz for Regulation(uA): 600; Iout/Iz(Max)(mA): 100; Temp Coeff(Typ)(ppm/ degree C): 34; VO Adj(Max)(V): 36; VO Adj(Min)(V): 2.495

## Sheet BiasSupply-LM61440-Q1.SchDoc
size 431 x 279 mm; Date: Not shown in title block; ApprovedBy: Not shown in title block; CheckedBy: Not shown in title block; Author: Not shown in title block; CompanyName: Not shown in title block; Engineer: Not shown in title block; Organization: Not shown in title block; Address1: Not shown in title block; Address2: Not shown in title block; Address3: Not shown in title block; Address4: Not shown in title block; DocumentNumber: 2; Revision: Use project parameter SCH_Rev; SheetNumber: 2; SheetTotal: 3; PageSetup: Record=PageOptions¦CenterHorizontal=True¦CenterVertical=True¦PrintScale=1.00¦XCorrection=1.00¦YCorrection=1.00¦PrintKind=0¦BorderSize=5000000¦LeftOffset=0¦BottomOffset=0¦Orientation=2¦PaperLength=1000¦PaperWidth=1000¦Scale=100¦PaperSource=15¦PrintQuality=600¦MediaType=1¦DitherType=10¦PaperKind=Letter¦PrintScaleMode=1
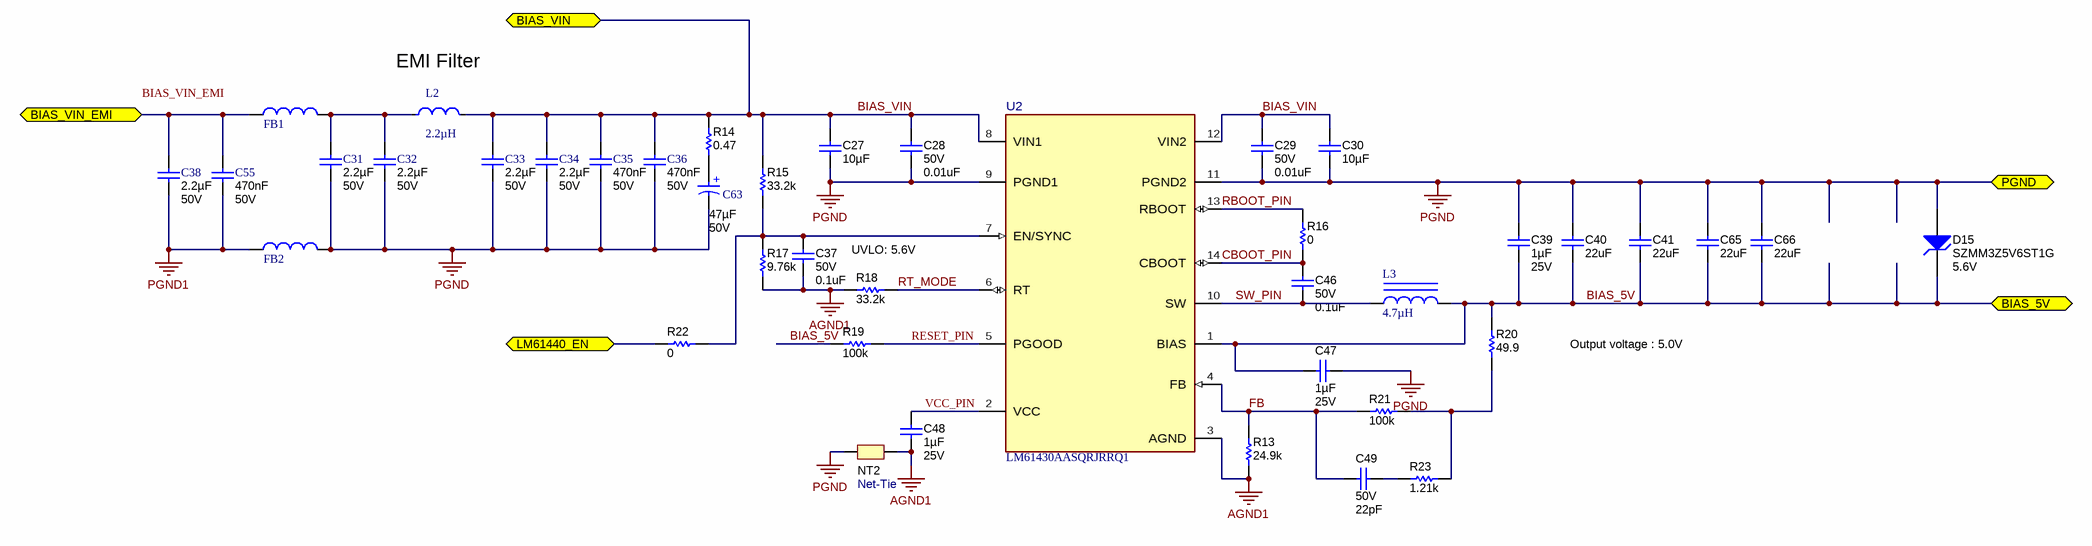
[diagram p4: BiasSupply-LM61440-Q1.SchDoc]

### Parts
C27  ValueDisplayed: 10µF  [1206_190]  (hidden comment: CGA5L1X7R1H106K160AC)
C28  VDC_V: 50V  ValueDisplayed: 0.01uF  [0402]  (hidden comment: CGA2B3X7R1H103K050BB)
C29  VDC_V: 50V  ValueDisplayed: 0.01uF  [0402]  (hidden comment: CGA2B3X7R1H103K050BB)
C30  ValueDisplayed: 10µF  [1206_190]  (hidden comment: CGA5L1X7R1H106K160AC)
C31  Cap_F: 2.2µF  VDC_V: 50V  [0805_HV]  (hidden comment: CF6)
C32  Cap_F: 2.2µF  VDC_V: 50V  [0805_HV]  (hidden comment: CF5)
C33  Cap_F: 2.2µF  VDC_V: 50V  [0805_HV]  (hidden comment: CF4)
C34  Cap_F: 2.2µF  VDC_V: 50V  [0805_HV]  (hidden comment: CF3)
C35  Cap_F: 470nF  VDC_V: 50V  [0603]  (hidden comment: CF2)
C36  Cap_F: 470nF  VDC_V: 50V  [0603]  (hidden comment: CF1)
C37  VDC_V: 50V  ValueDisplayed: 0.1uF  [0402]  (hidden comment: GCM155R71H104KE02D)
C38  Cap_F: 2.2µF  VDC_V: 50V  [0805_HV]  (hidden comment: CF6)
C39  Cap_F: 1µF  VDC_V: 25V  [0603S]  (hidden comment: CGA3E1X7R1E105K080AC)
C40  ValueDisplayed: 22uF  [1206_180]  (hidden comment: GCM31CR71A226KE02L)
C41  ValueDisplayed: 22uF  [1206_180]  (hidden comment: GCM31CR71A226KE02L)
C46  VDC_V: 50V  ValueDisplayed: 0.1uF  [0402]  (hidden comment: GCM155R71H104KE02D)
C47  Cap_F: 1µF  VDC_V: 25V  [0603S]  (hidden comment: CGA3E1X7R1E105K080AC)
C48  Cap_F: 1µF  VDC_V: 25V  [0603S]  (hidden comment: CGA3E1X7R1E105K080AC)
C49  VDC_V: 50V  ValueDisplayed: 22pF  [0402]  (hidden comment: CGA2B2NP01H220J050BA)
C55  Cap_F: 470nF  VDC_V: 50V  [0603]  (hidden comment: CF2)
C63  Cap_F: 47µF  Rated Voltage (DC): 50V  [WCAP-ASLI_D8H6.5]  (hidden comment: 865080649013)
C65  ValueDisplayed: 22uF  [1206_180]  (hidden comment: GCM31CR71A226KE02L)
C66  ValueDisplayed: 22uF  [1206_180]  (hidden comment: GCM31CR71A226KE02L)
D15  SZMM3Z5V6ST1G  value 5.6V  [SOD-323]
FB1  782763601  [WE-CBA_1206_L3.2W1.6H1.1_HC]  (value not drawn)
FB2  782763601  [WE-CBA_1206_L3.2W1.6H1.1_HC]  (value not drawn)
L2  Ind_H: 2.2µH  [FP-744316220_SMD2-MFG]  (hidden comment: 744316220)
L3  ValueDisplayed: 4.7µH  [WE-XHMI_6060]  (hidden comment: 74439346047)
NT2  Net-Tie  [Net-Tie_10mil]  (net tie, no BOM)
R13  ValueDisplayed: 24.9k  [0402]  (hidden comment: CRCW040224K9FKED)
R14  ValueDisplayed: 0.47  [0805_HV]  (hidden comment: ERJ-6RQFR47V)
R15  ValueDisplayed: 33.2k  [0402]  (hidden comment: CRCW040233K2FKED)
R16  ValueDisplayed: 0  [0402]  (hidden comment: CRCW04020000Z0ED)
R17  ValueDisplayed: 9.76k  [0402]  (hidden comment: CRCW04029K76FKED)
R18  ValueDisplayed: 33.2k  [0402]  (hidden comment: CRCW040233K2FKED)
R19  ValueDisplayed: 100k  [0402]  (hidden comment: CRCW0402100KDHEDP)
R20  ValueDisplayed: 49.9  [0402]  (hidden comment: CRCW040249R9FKED)
R21  ValueDisplayed: 100k  [0402]  (hidden comment: CRCW0402100KDHEDP)
R22  ValueDisplayed: 0  [0402]  (hidden comment: CRCW04020000Z0ED)
R23  ValueDisplayed: 1.21k  [0402]  (hidden comment: CRCW04021K21FKED)
U2  LM61430AASQRJRRQ1  [RJR0014A-MFG]

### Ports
BIAS_5V (bidir), BIAS_VIN (bidir), BIAS_VIN_EMI (bidir), LM61440_EN (bidir), PGND (bidir)

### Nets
AGND1: C37.2 C48.2 NT2.2 R13.1 R17.1 R18.1 U2.3(AGND)
PGND: C27.2 C28.2 C29.2 C30.2 C31.2 C32.2 C33.2 C34.2 C35.2 C36.2 C39.2 C40.1 C41.1 C47.2 C63.2(N) C65.1 C66.1 D15.2(A) FB2.2 NT2.1 U2.9(PGND1) U2.11(PGND2) ; port PGND
PGND1: C38.2 C55.2 FB2.1
BIAS_5V: C39.1 C40.2 C41.2 C47.1 C65.2 C66.2 D15.1(K) L3.2 R19.1 R20.2 U2.1(BIAS) ; port BIAS_5V
BIAS_VIN: C27.1 C28.1 C29.1 C30.1 C33.1 C34.1 C35.1 C36.1 L2.2 R14.2 R15.2 U2.8(VIN1) U2.12(VIN2) ; port BIAS_VIN
BIAS_VIN_EMI: C38.1 C55.1 FB1.1 ; port BIAS_VIN_EMI
CBOOT_PIN: C46.1 R16.1 U2.14(CBOOT)
FB: C49.2 R13.2 R21.1 U2.4(FB)
LM61440_EN: R22.1 ; port LM61440_EN
RBOOT_PIN: R16.2 U2.13(RBOOT)
RESET_PIN: R19.2 U2.5(PGOOD)
RT_MODE: R18.2 U2.6(RT)
SW_PIN: C46.2 L3.1 U2.10(SW)
VCC_PIN: C48.1 U2.2(VCC)
NetC31_1: C31.1 C32.1 FB1.2 L2.1
NetC37_1: C37.1 R15.1 R17.2 R22.2 U2.7(EN/SYNC)
NetC49_1: C49.1 R23.2
NetC63_1: C63.1(P) R14.1
NetR20_1: R20.1 R21.2 R23.1

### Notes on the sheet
- (near L2) EMI Filter
- UVLO: 5.6V
- Output voltage : 5.0V
- Labels drawn without touching a wire or pin: BIAS_VIN_EMI

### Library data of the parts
C27 C30 = CMP-0085950-1: as C50 on sheet BiasSupply-LM74202-Q1
C28 C29 = CMP-0006324-2: CAP, CERM, 0.01 uF, 50 V, +/- 10%, X7R, AEC-Q200 Grade 1, 0402; Manufacturer: TDK; TaMin_C: -55°C; ESR_ohm: 0.333065; Polarized: N; SizeAreaWB_mm2: 3; Value1: 0.333065 ohm; U/M: EA; Value: 0.01uF; TaMax_C: 125°C; SizeZ_mm: 0.6; SizeX_mm: 1; SizeY_mm: 0.5; AEC Qualified: Y; Cap_F: 10nF; IRMS_A: 323.373mA; AEC Category: Q200
C31-C34 C38 = CMP-0007977-2: CAP, CERM, 2.2 uF, 50 V, +/- 10%, X7R, AEC-Q200 Grade 1, 0805; Manufacturer: TDK; PartNumber: CGA4J3X7R1H225K125AB; TaMin_C: -55°C; ESR_ohm: 3.288m; Polarized: N; SizeAreaWB_mm2: 6.75; Value1: 0.003288 ohm; U/M: EA; Value: 2.2uF; TaMax_C: 125°C; SizeZ_mm: 1.45; SizeX_mm: 2; SizeY_mm: 1.25; Cap_Case: 0805; SizeArea_mm2: 2.5; CompType: Capacitor; AEC Qualified: Y; IRMS_A: 3.60029A; AEC Grade: 1; AEC Category: Q200
C35 C36 C55 = CMP-0007097-4: CAP, CERM, 0.47 uF, 50 V, +/- 10%, X7R, AEC-Q200 Grade 1, 0603; Manufacturer: TDK; PartNumber: CGA3E3X7R1H474K080AE; TaMin_C: -55°C; Polarized: N; SizeAreaWB_mm2: 4.68; Value1: Unknown; U/M: EA; Value: 0.47uF; TaMax_C: 125°C; SizeZ_mm: 1; SizeX_mm: 1.6; SizeY_mm: 0.8; SizeArea_mm2: 1.28; CompType: Capacitor; AEC Qualified: Y; AEC Category: Q200
C37 C46 = CMP-0006356-2: as C8 on sheet BiasSupply-TPS552872-Q1
C39 C47 C48 = CMP-0076705-2: as C6 on sheet BiasSupply-TPS552872-Q1
C40 C41 C65 C66 = CMP-0008811-3: CAP, CERM, 22 uF, 10 V, +/- 10%, X7R, AEC-Q200 Grade 1, 1206; Manufacturer: MuRata; SizeX_mm: 3.2; SizeArea_mm2: 5.12; Polarized: N; SizeY_mm: 1.6; Value2: 10V; TaMin_C: -55°C; SizeZ_mm: 1.8; Cap_Case: 1206; AEC Grade: 1; Value1: Unknown; U/M: EA; AEC Qualified: Y; SizeAreaWB_mm2: 10.92; AEC Category: Q200; Value: 22uF; Cap_F: 22µF; TaMax_C: 125°C
C49 = CMP-0006311-2: CAP, CERM, 22 pF, 50 V, +/- 5%, C0G/NP0, AEC-Q200 Grade 1, 0402; Manufacturer: TDK; TaMin_C: -55°C; Polarized: N; SizeAreaWB_mm2: 3; Value1: Unknown; U/M: EA; Value: 22pF; TaMax_C: 125°C; SizeZ_mm: 0.6; SizeX_mm: 1; SizeY_mm: 0.5; AEC Qualified: Y; AEC Category: Q200
C63 = CMP-0107044-1: WCAP-ASLI Aluminum Electrolytic Capacitor, V-Chip, D8 x H6.5mm, 47uF, 50V; Manufacturer: Wurth Elektronik; Capacitance Tolerance: +/-20%; Dissipation Factor: 12%; Endurance: 2000h; Leakage Current: 23.5uA; Ripple Current: 240mA; Technical Reference: ASEE065470M050DVCTBB000
D15 = CMP-0085742-1: Diode, Zener, 5.6 V, 300 mW, AEC-Q101, SOD-323; Manufacturer: ON Semiconductor; SizeAreaWB_mm2: 8.695; SizeY_mm: 1.35; SizeZ_mm: 1; AEC Qualified: Y; SizeArea_mm2: 3.645; Value1: 0.3W; Power_W: 300mW; RJA_CperW: 416; AEC Category: Q101; SizeX_mm: 2.7
FB1 FB2 = CMP-0066650-1: WE-CBA SMT EMI Suppression Ferrite Bead, size 1206, 600Ohm, 2.5A; Manufacturer: Wurth Elektronik; Case/Size Code: 1206; DC Resistance Max: 0.048Ohm; Impedance Max: 650Ohm; Type: High Current
L2 = CMP-0086950-1: 2.2µH Shielded Molded Inductor 7.5A 11.3mOhm Max 2-SMD; Manufacturer: Wurth Electronics; SizeZ_mm: 4.3mm; DCR_ohm: 0.0113; Symbol Name: SYM-744316220; AEC Grade: Grade 0; AEC Qualified: Yes
L3 = CMP-0085367-1: Inductor, Shielded, Hyperflux, 4.7 µH, 7.4 A, 0.0143 ohm, SMD; Manufacturer: Wurth Elektronik; DCR_ohm: 0.0143; Value2: 7.4A; SizeArea_mm2: 42.8925; SizeX_mm: 6.65; Isat: 14.7A @ 30% inductance drop; AEC Category: Q200; Value: 4.7uH; SizeY_mm: 6.45; SizeZ_mm: 6.1; AEC Qualified: N; Irms: 7.4A @ 40C rise; SizeAreaWB_mm2: 73.0925
NT2 = CMP-0078142-4: Single point connection between nets.
R13 = CMP-0026196-2: as R10 on sheet BiasSupply-TPS552872-Q1
R14 = CMP-0021842-3: RES, 0.47, 1%, 0.125 W, AEC-Q200 Grade 0, 0805; Manufacturer: Panasonic; Power_W: 125mW; TempCo: 250 ppm/C; Value_Code: R470; Value: 0.47; EIA_Code: E96; SizeX_mm: 2; SizeY_mm: 1.25; SizeZ_mm: 1.45; Value2: 0.125W; SizeArea_mm2: 2.5; AEC Qualified: Y; AEC Category: Q200; AEC Grade: 0; SizeAreaWB_mm2: 6.75
R15 R18 = CMP-0026298-2: RES, 33.2 k, 1%, 0.063 W, AEC-Q200 Grade 0, 0402; Manufacturer: Vishay-Dale; Power_W: 63mW; TempCo: 100 ppm/C; Value_Code: 33k2; Value: 33.2k; EIA_Code: E96; SizeX_mm: 1; SizeY_mm: 0.5; SizeZ_mm: 0.6; Value2: 0.063W; AEC Qualified: Y; VDC_V: 50V; AEC Category: Q200; AEC Grade: 0
R16 R22 = CMP-0026822-3: as R5 on sheet BiasSupply-TPS552872-Q1
R17 = CMP-0026622-3: as R39 on sheet BiasSupply-SN6507-Q1
R19 R21 = CMP-0026768-2: RES, 100 k, 0.5%, 0.063 W, AEC-Q200 Grade 0, 0402; Manufacturer: Vishay-Dale; Power_W: 63mW; TempCo: 50 ppm/C; Value: 100k; EIA_Code: E192; SizeX_mm: 1; SizeY_mm: 0.5; SizeZ_mm: 0.6; Value2: 0.063W; AEC Qualified: Y; VDC_V: 50V; AEC Category: Q200; AEC Grade: 0
R20 = CMP-0026404-2: RES, 49.9, 1%, 0.063 W, AEC-Q200 Grade 0, 0402; Manufacturer: Vishay-Dale; Power_W: 63mW; TempCo: 100 ppm/C; Value_Code: 49R9; Value: 49.9; EIA_Code: E96; SizeX_mm: 1; SizeY_mm: 0.5; SizeZ_mm: 0.6; Value2: 0.063W; AEC Qualified: Y; VDC_V: 50V; AEC Category: Q200; AEC Grade: 0
R23 = CMP-0026079-3: RES, 1.21 k, 1%, 0.063 W, AEC-Q200 Grade 0, 0402; Manufacturer: Vishay-Dale; Power_W: 63mW; TempCo: 100 ppm/C; Value_Code: 1k21; Value: 1.21k; EIA_Code: E96; SizeX_mm: 1; SizeY_mm: 0.5; SizeZ_mm: 0.6; Value2: 0.063W; AEC Qualified: Y; VDC_V: 50V; AEC Category: Q200; AEC Grade: 0
U2 = CMP-0092866-1: 3-V to 36-V, Low EMI Synchronous Step-Down Converter; Manufacturer: Texas Instruments; AEC Grade: Grade 1; Output Type: AdjustableProgrammable; Switching Frequency: 200-2200kHz; Output Voltage: 1-34.2V; Max Duty Cycle: 98%; Number Of Outputs: 1; Max Supply Voltage: 36V; SizeZ_mm: 1mm; Min Supply Voltage: 3V; Standoff Height: 0mm; TJmax_C: +150°C; Switching Topology: Buck; AEC Qualified: Yes; Nominal Supply Current: 9uA

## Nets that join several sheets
BIAS_ISO_GND1: BiasSupply-LM74202-Q1 (J2.2), BiasSupply-SN6507-Q1 (10 pins)
BIAS_ISO_GND2: BiasSupply-LM74202-Q1 (J2.6), BiasSupply-SN6507-Q1 (10 pins)
PGND: BiasSupply-TPS552872-Q1 (16 pins), BiasSupply-LM74202-Q1 (J1.5 J3.2 J3.3 J3.4), BiasSupply-SN6507-Q1 (24 pins), BiasSupply-LM61440-Q1 (22 pins)
PGND1: BiasSupply-LM74202-Q1 (10 pins), BiasSupply-LM61440-Q1 (C38.2 C55.2 FB2.1)
BIAS_5V: BiasSupply-LM74202-Q1 (J3.1), BiasSupply-LM61440-Q1 (11 pins)
BIAS_12V: BiasSupply-TPS552872-Q1 (11 pins), BiasSupply-LM74202-Q1 (J3.5)
BIAS_ISO_12V_1: BiasSupply-LM74202-Q1 (J2.3), BiasSupply-SN6507-Q1 (5 pins)
BIAS_ISO_12V_2: BiasSupply-LM74202-Q1 (J2.7), BiasSupply-SN6507-Q1 (5 pins)
BIAS_ISO_-5V_1: BiasSupply-LM74202-Q1 (J2.1), BiasSupply-SN6507-Q1 (7 pins)
BIAS_ISO_-5V_2: BiasSupply-LM74202-Q1 (J2.5), BiasSupply-SN6507-Q1 (7 pins)
BIAS_VIN: BiasSupply-TPS552872-Q1 (6 pins), BiasSupply-SN6507-Q1 (10 pins), BiasSupply-LM61440-Q1 (13 pins)
BIAS_VIN_EMI: BiasSupply-LM74202-Q1 (8 pins), BiasSupply-LM61440-Q1 (C38.1 C55.1 FB1.1)
LM61440_EN: BiasSupply-LM74202-Q1 (J1.4), BiasSupply-LM61440-Q1 (R22.1)
SN6507_EN1: BiasSupply-LM74202-Q1 (J1.1), BiasSupply-SN6507-Q1 (R56.1)
SN6507_EN2: BiasSupply-LM74202-Q1 (J1.2), BiasSupply-SN6507-Q1 (R57.1)
TPS552872_EN: BiasSupply-TPS552872-Q1 (R5.1), BiasSupply-LM74202-Q1 (J1.3)

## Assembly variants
PMP41125 BiasSupply: not fitted R5 R22 R26 R36 R41 R45 R46 R48 R49 R54 R59 U5 U7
